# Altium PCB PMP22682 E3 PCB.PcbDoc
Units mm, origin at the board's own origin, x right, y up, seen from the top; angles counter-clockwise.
Board outline 97.75 x 106 mm, 6 copper layers (Top Layer, Signal Layer 1, Signal Layer 2, Signal Layer 3, Signal Layer 4, Bottom Layer), stack 2.5 mm thick; 97 components, 38 nets, 279 pads, 103 vias.
Unrouted connection lines stored in the file: 1.
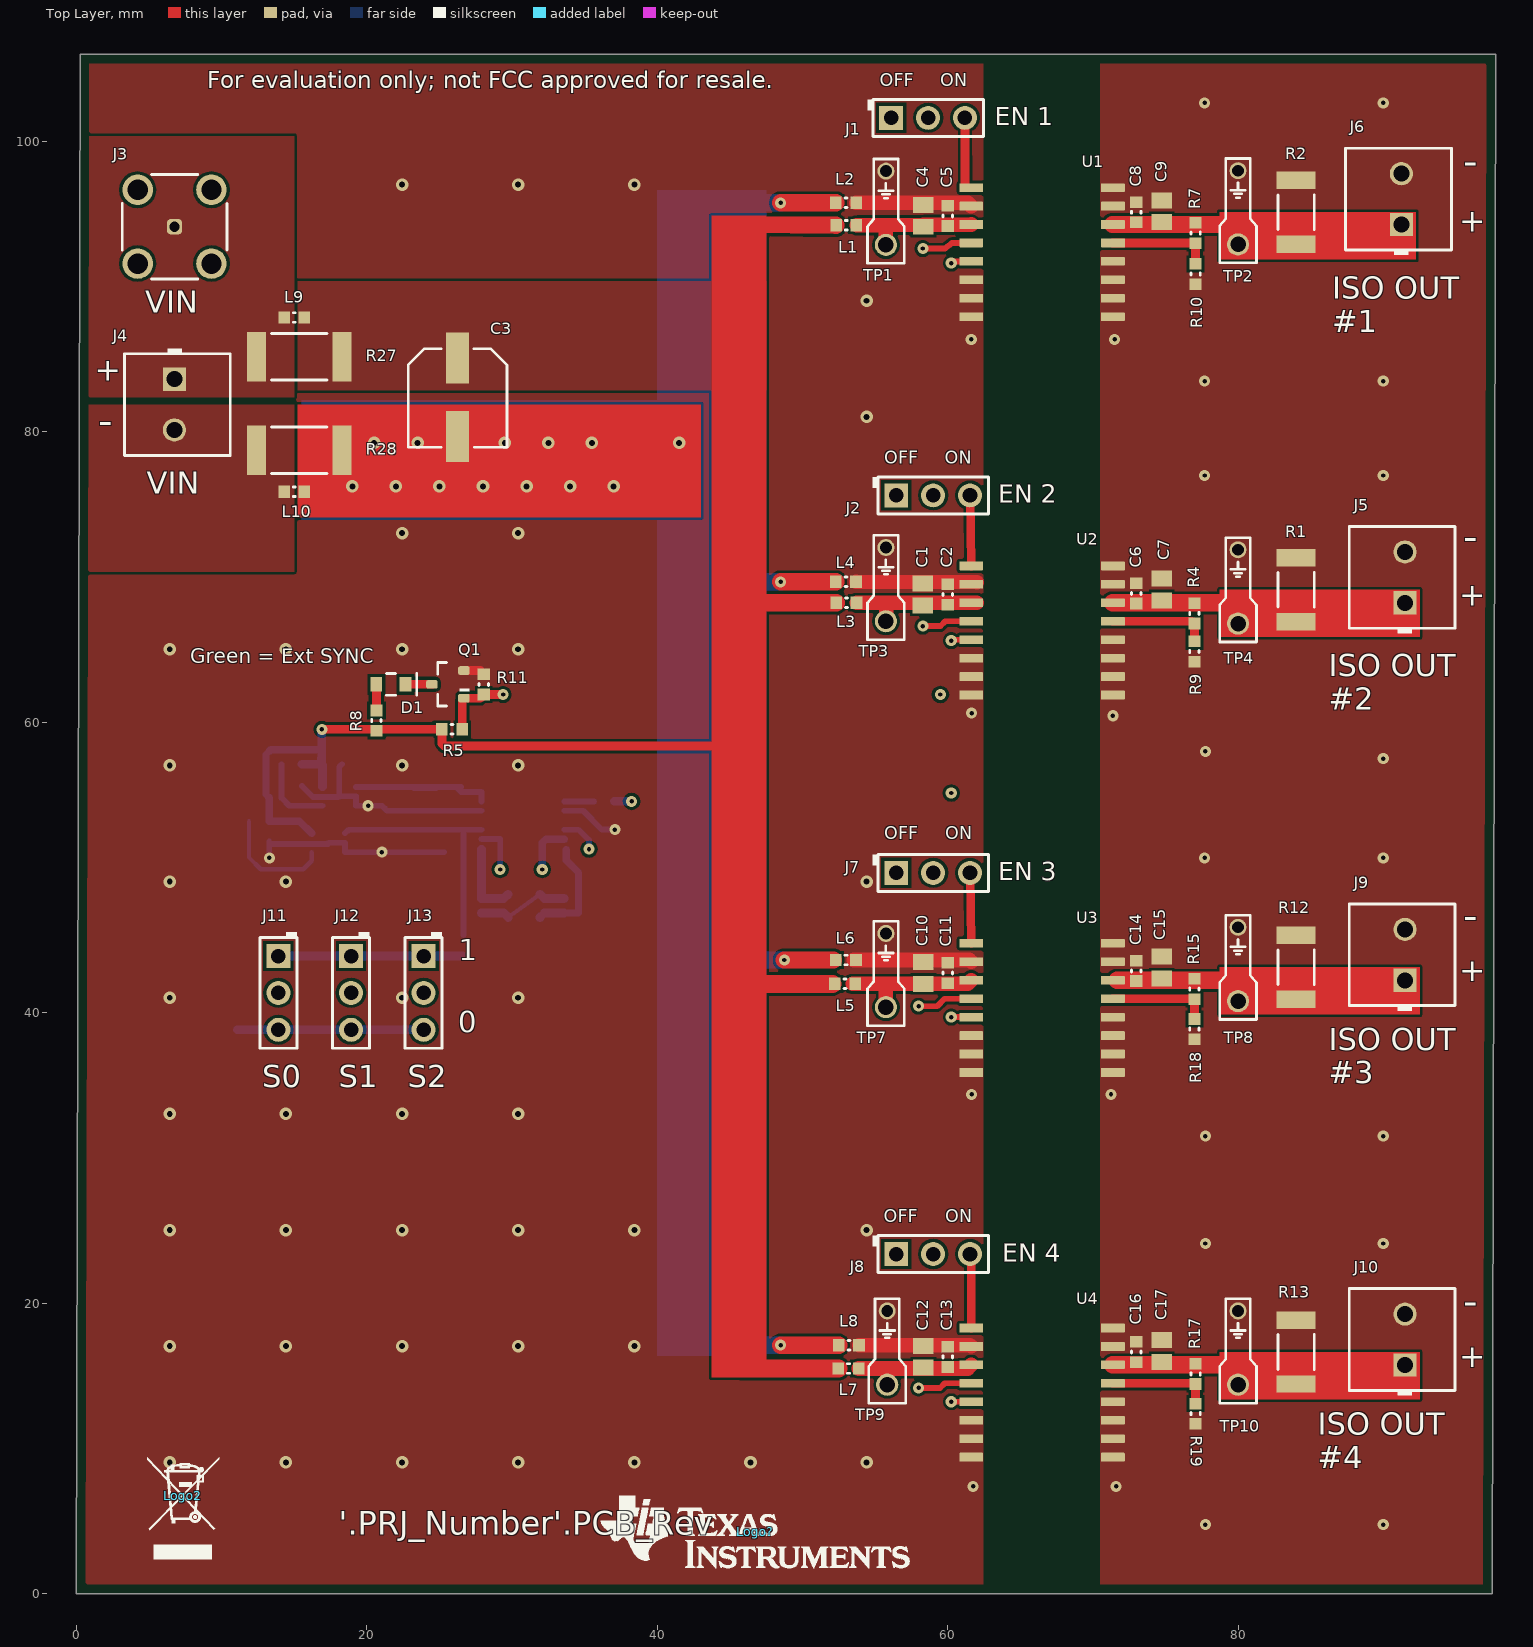
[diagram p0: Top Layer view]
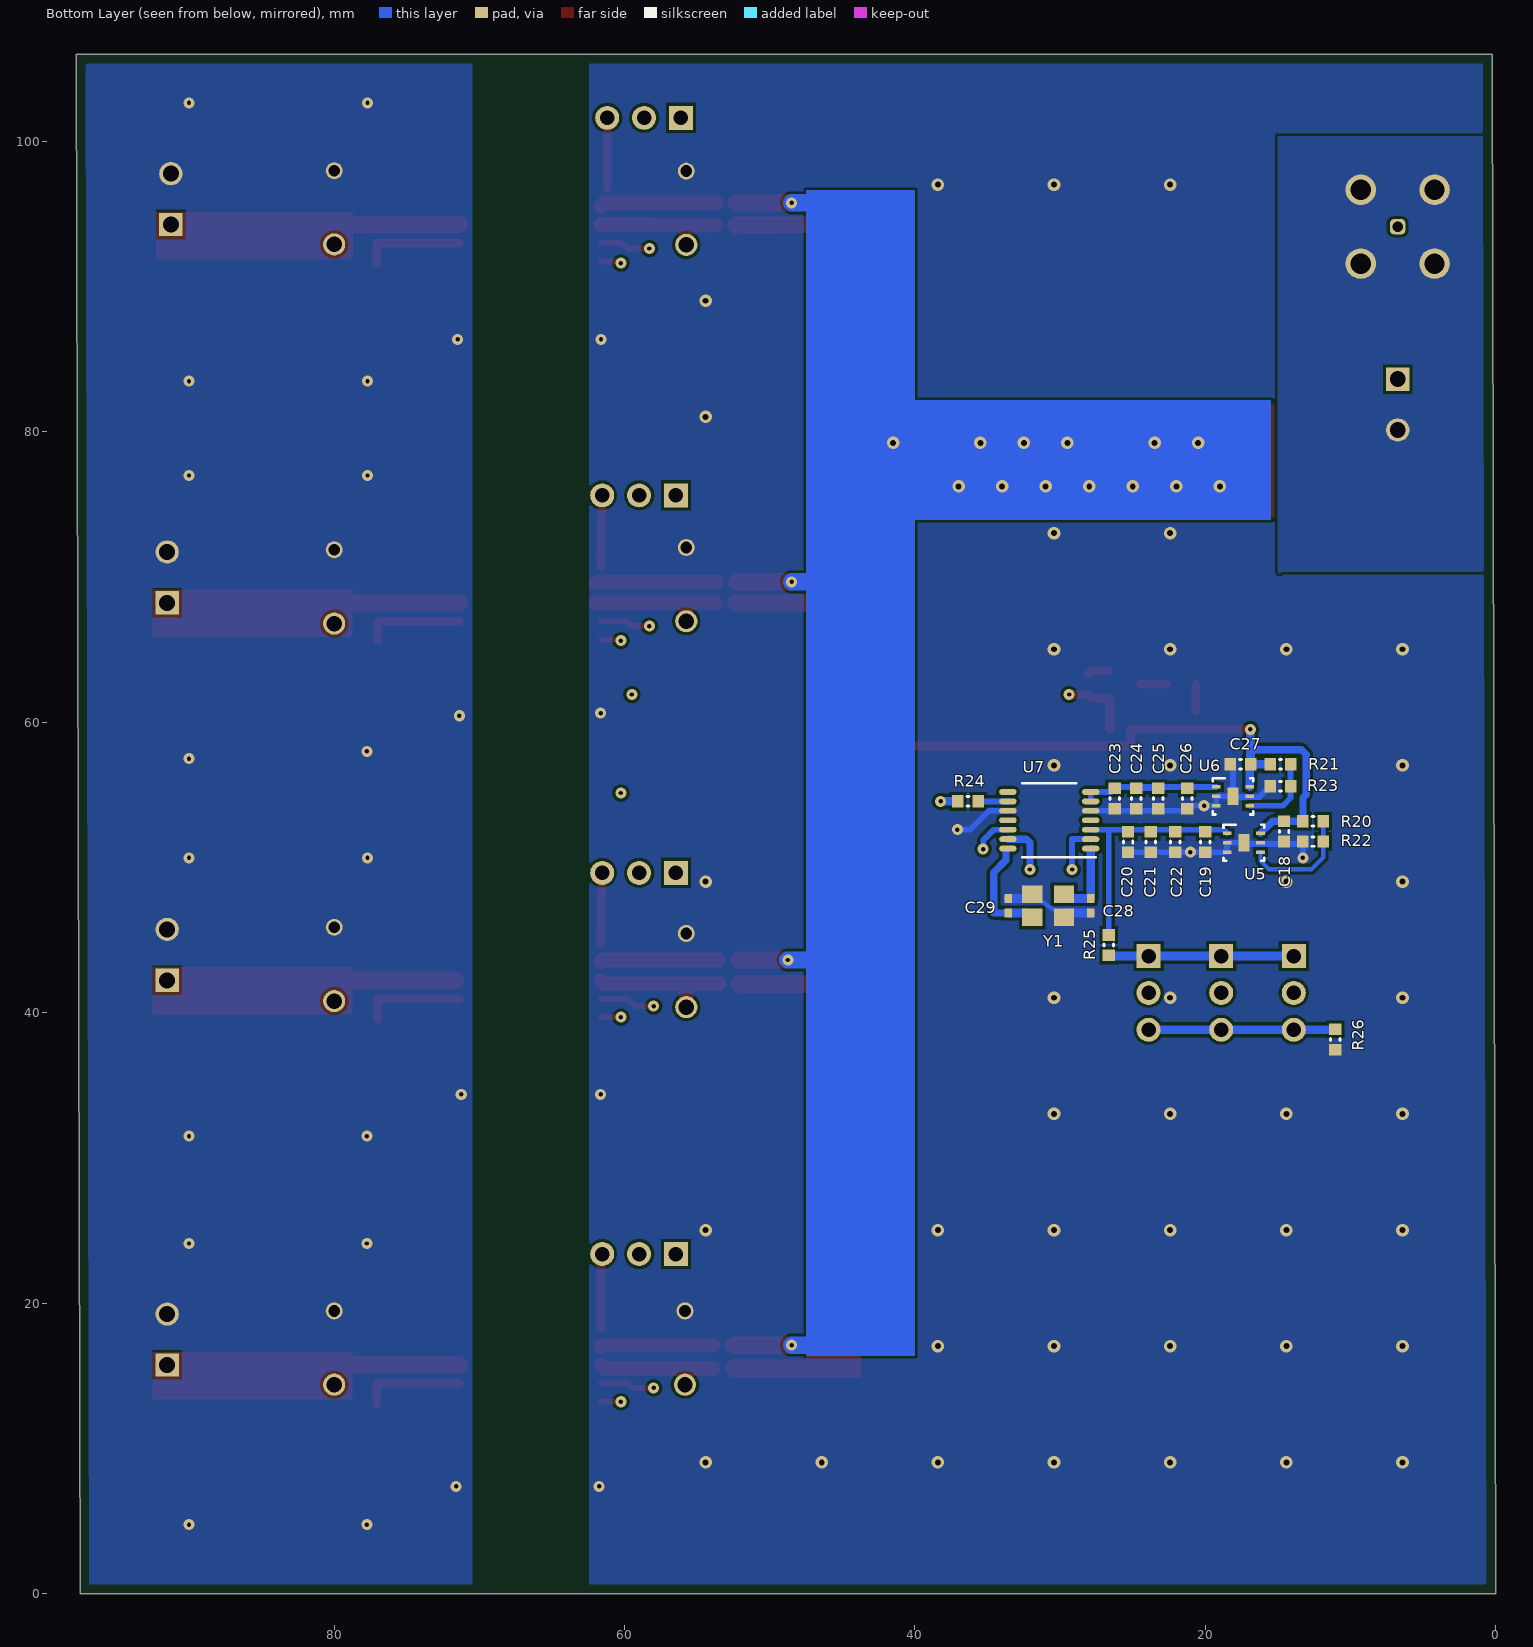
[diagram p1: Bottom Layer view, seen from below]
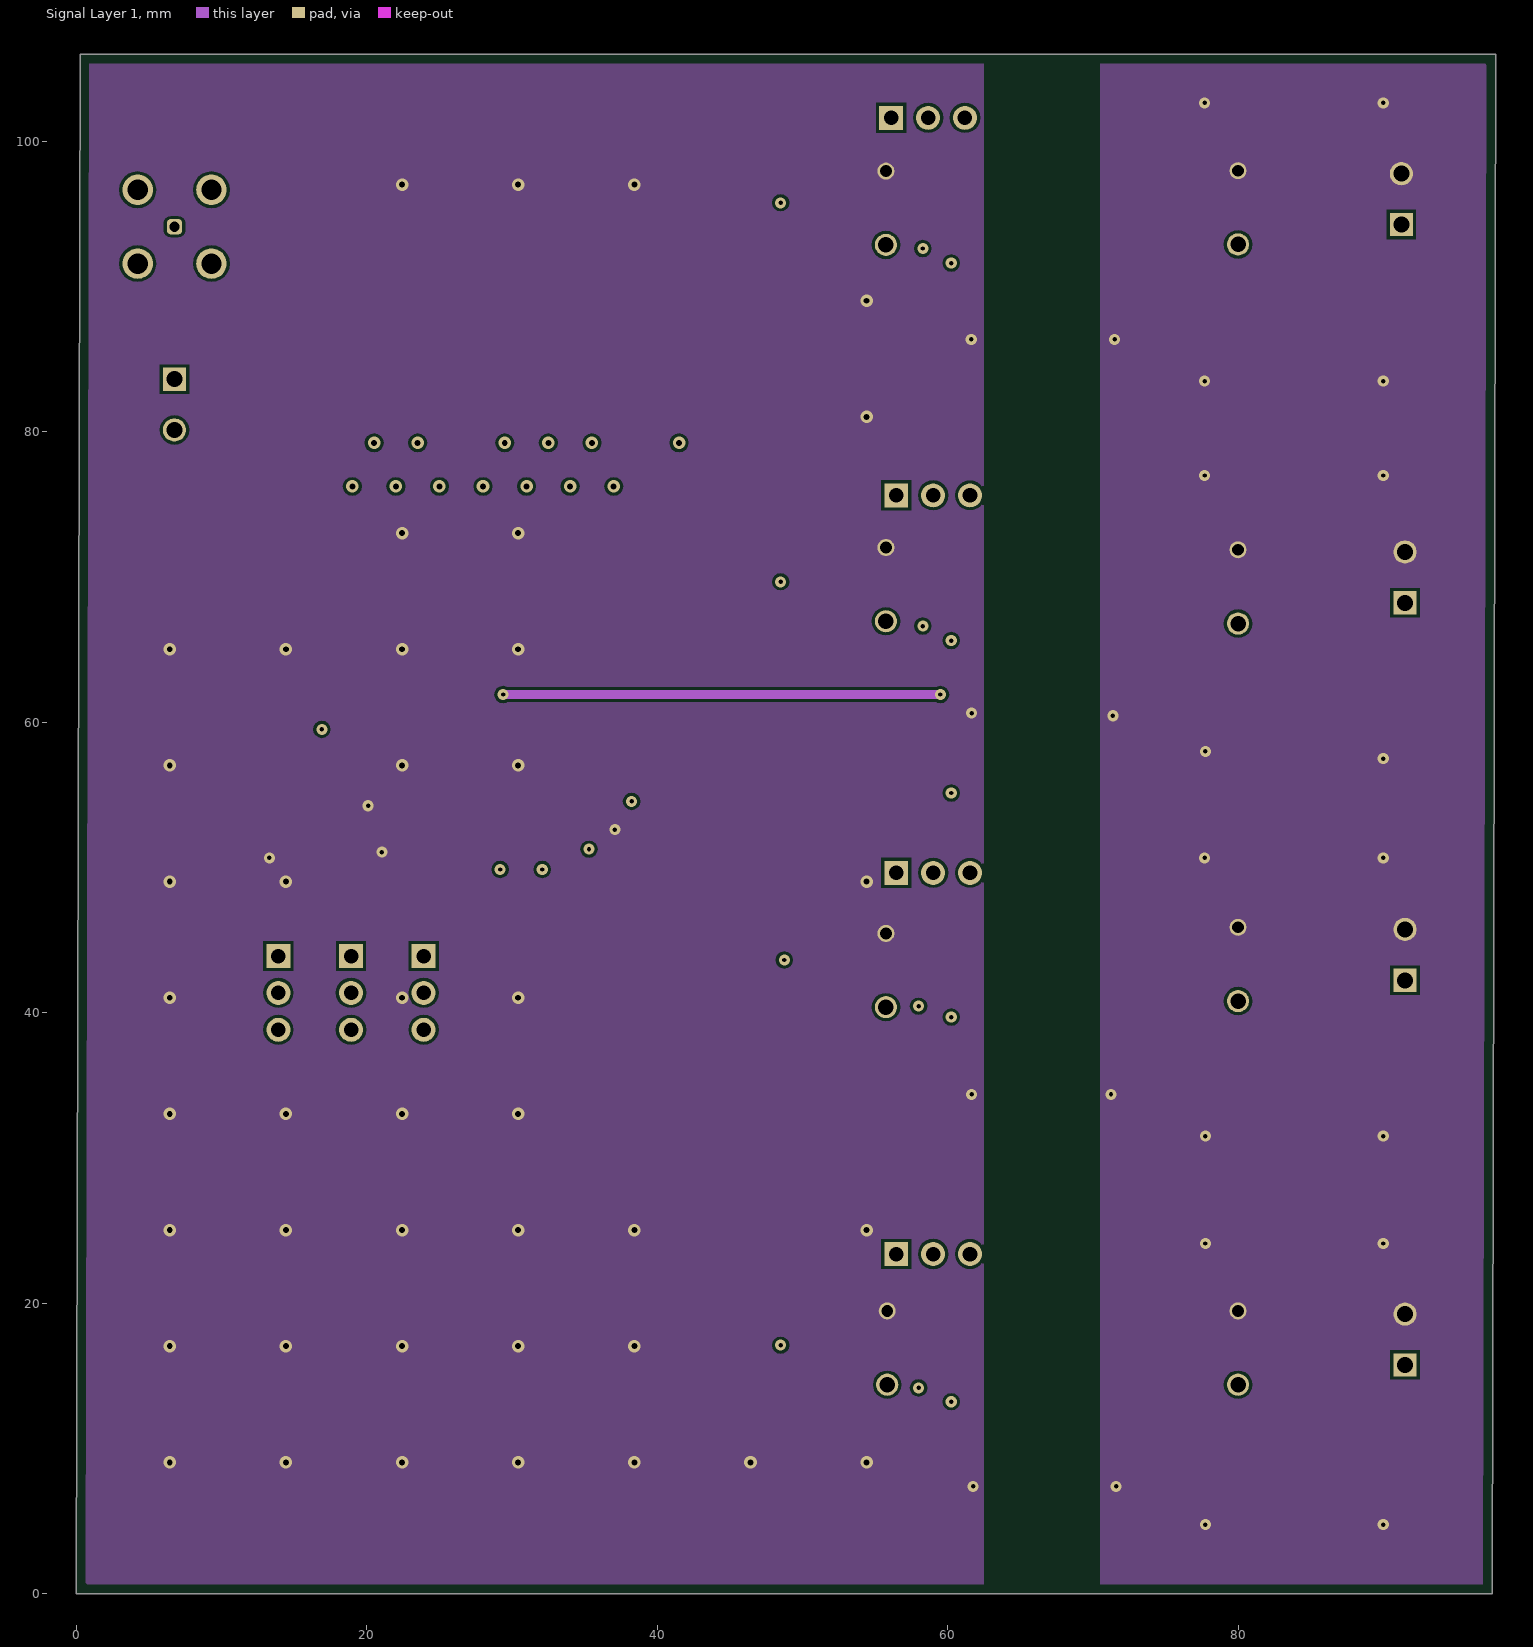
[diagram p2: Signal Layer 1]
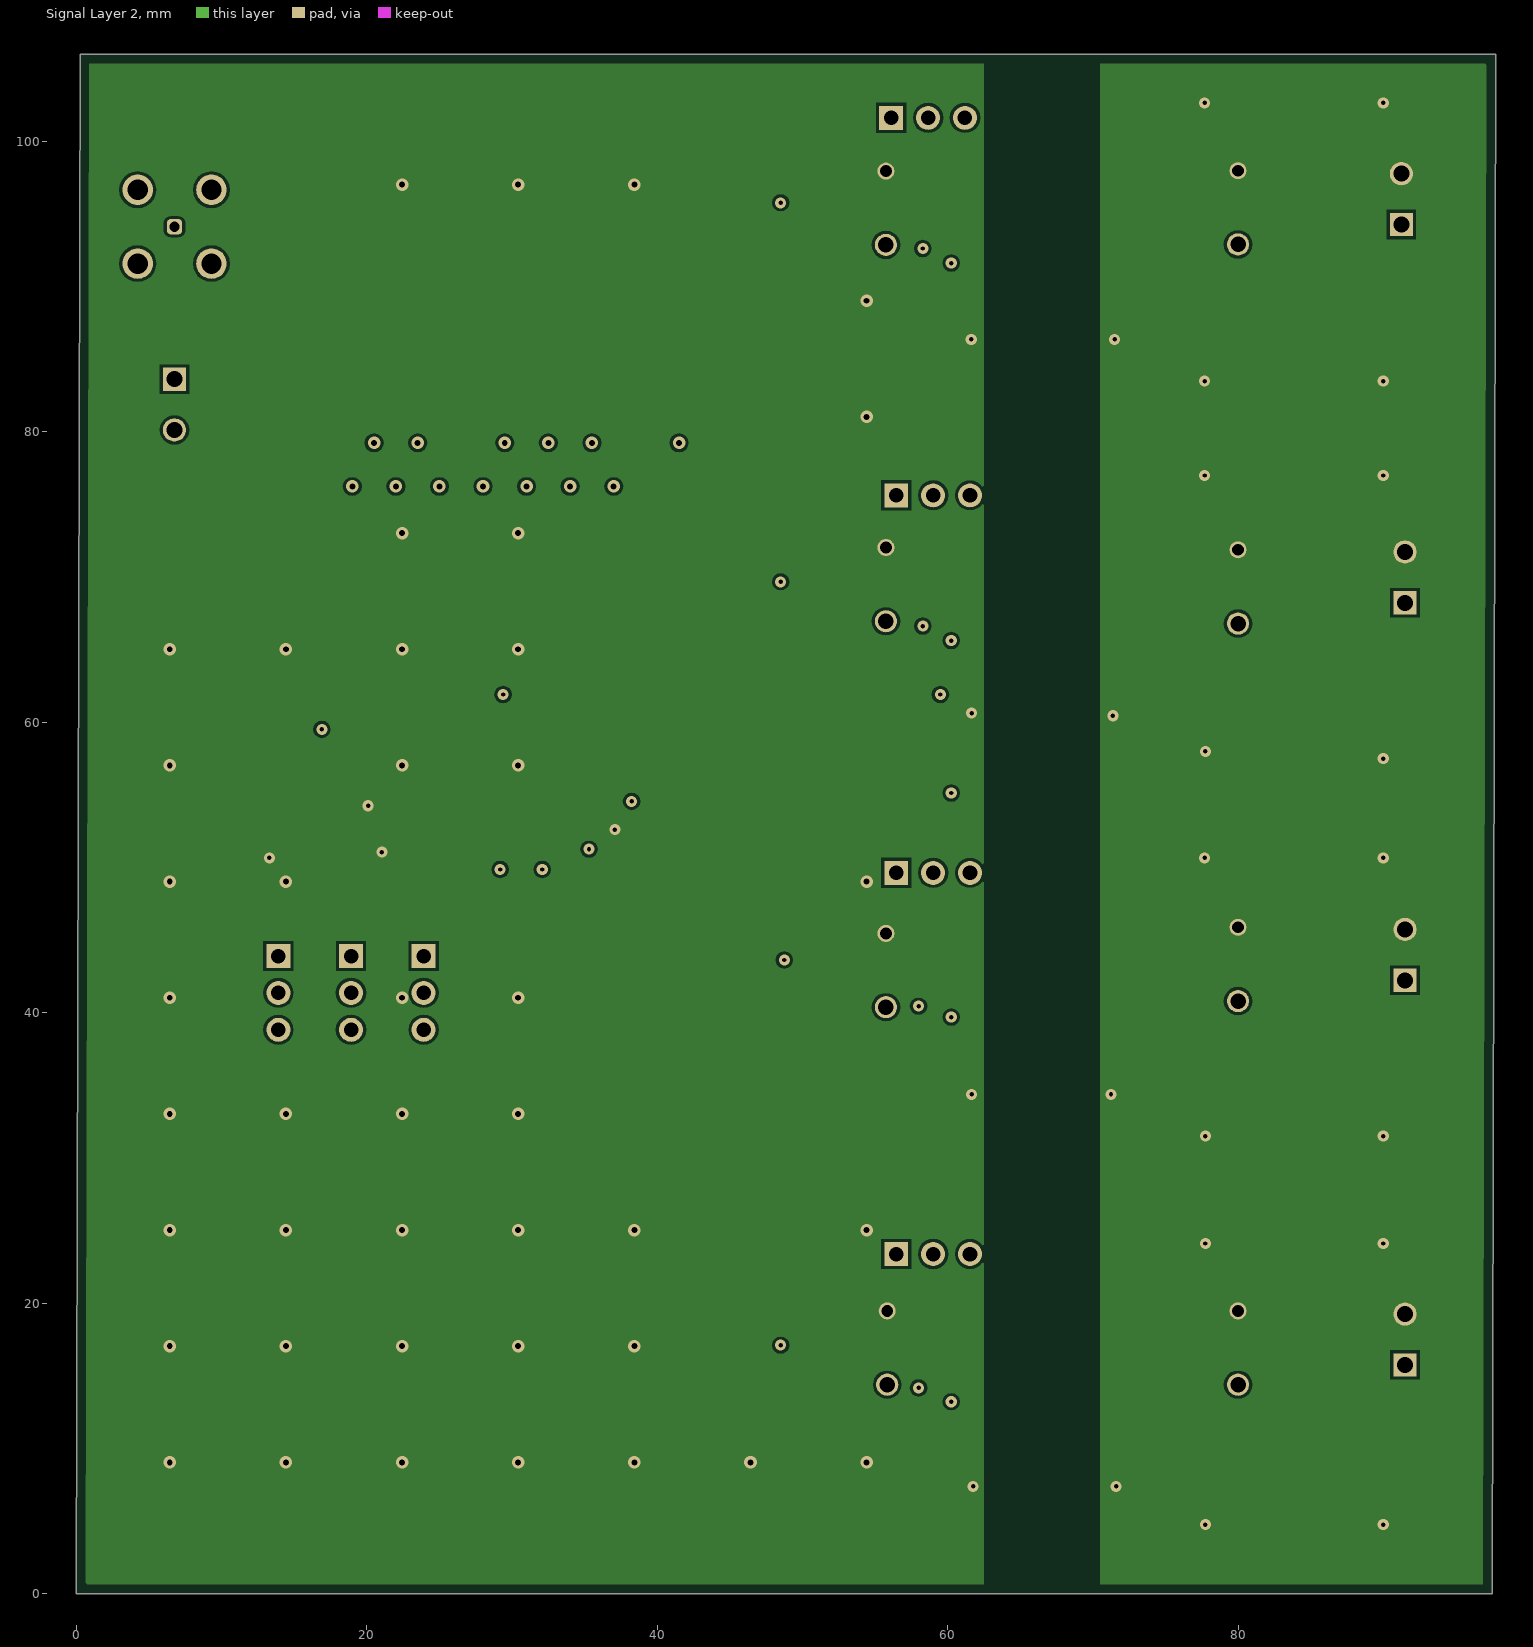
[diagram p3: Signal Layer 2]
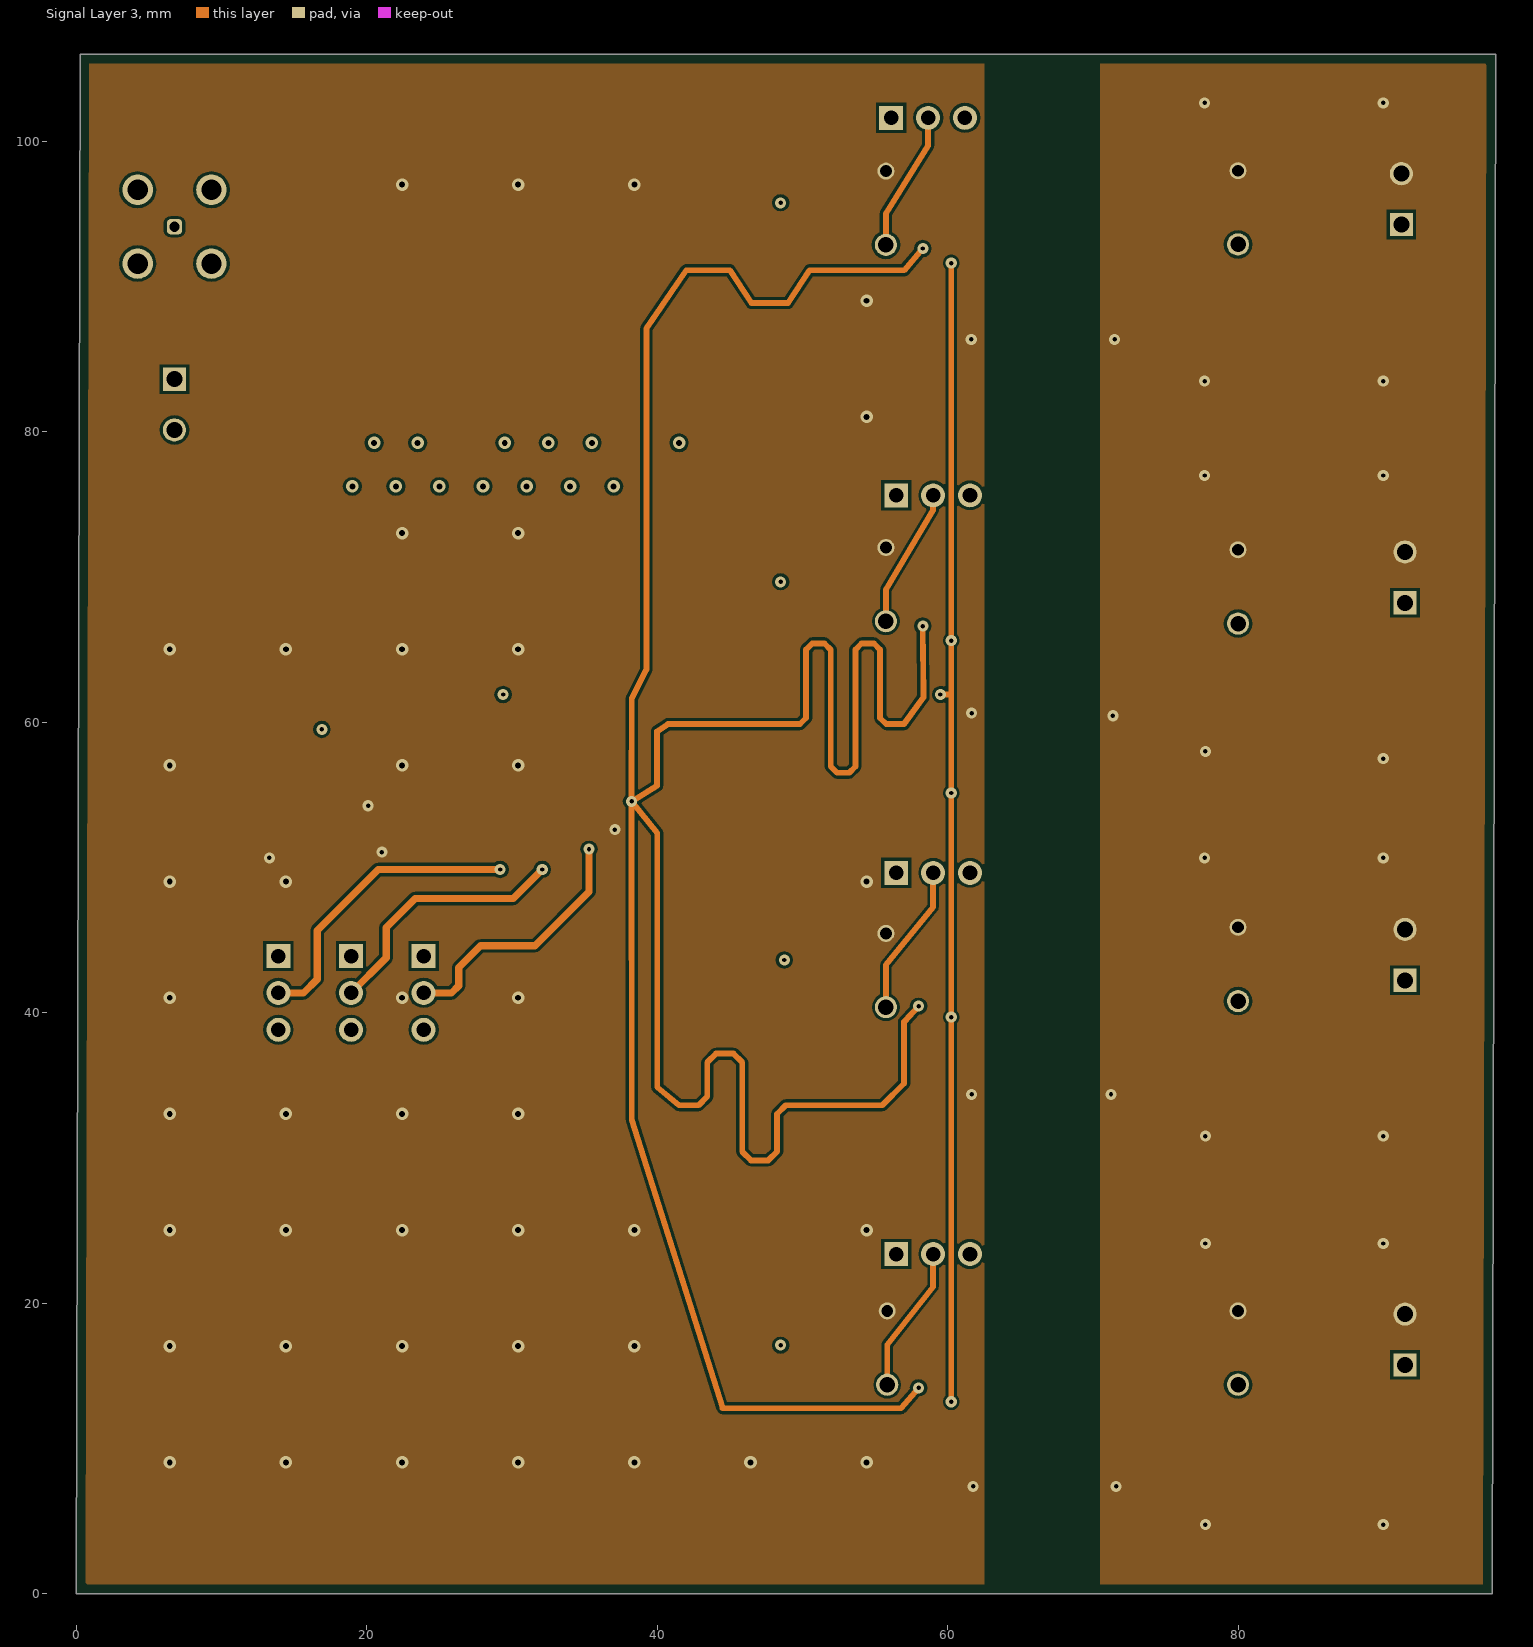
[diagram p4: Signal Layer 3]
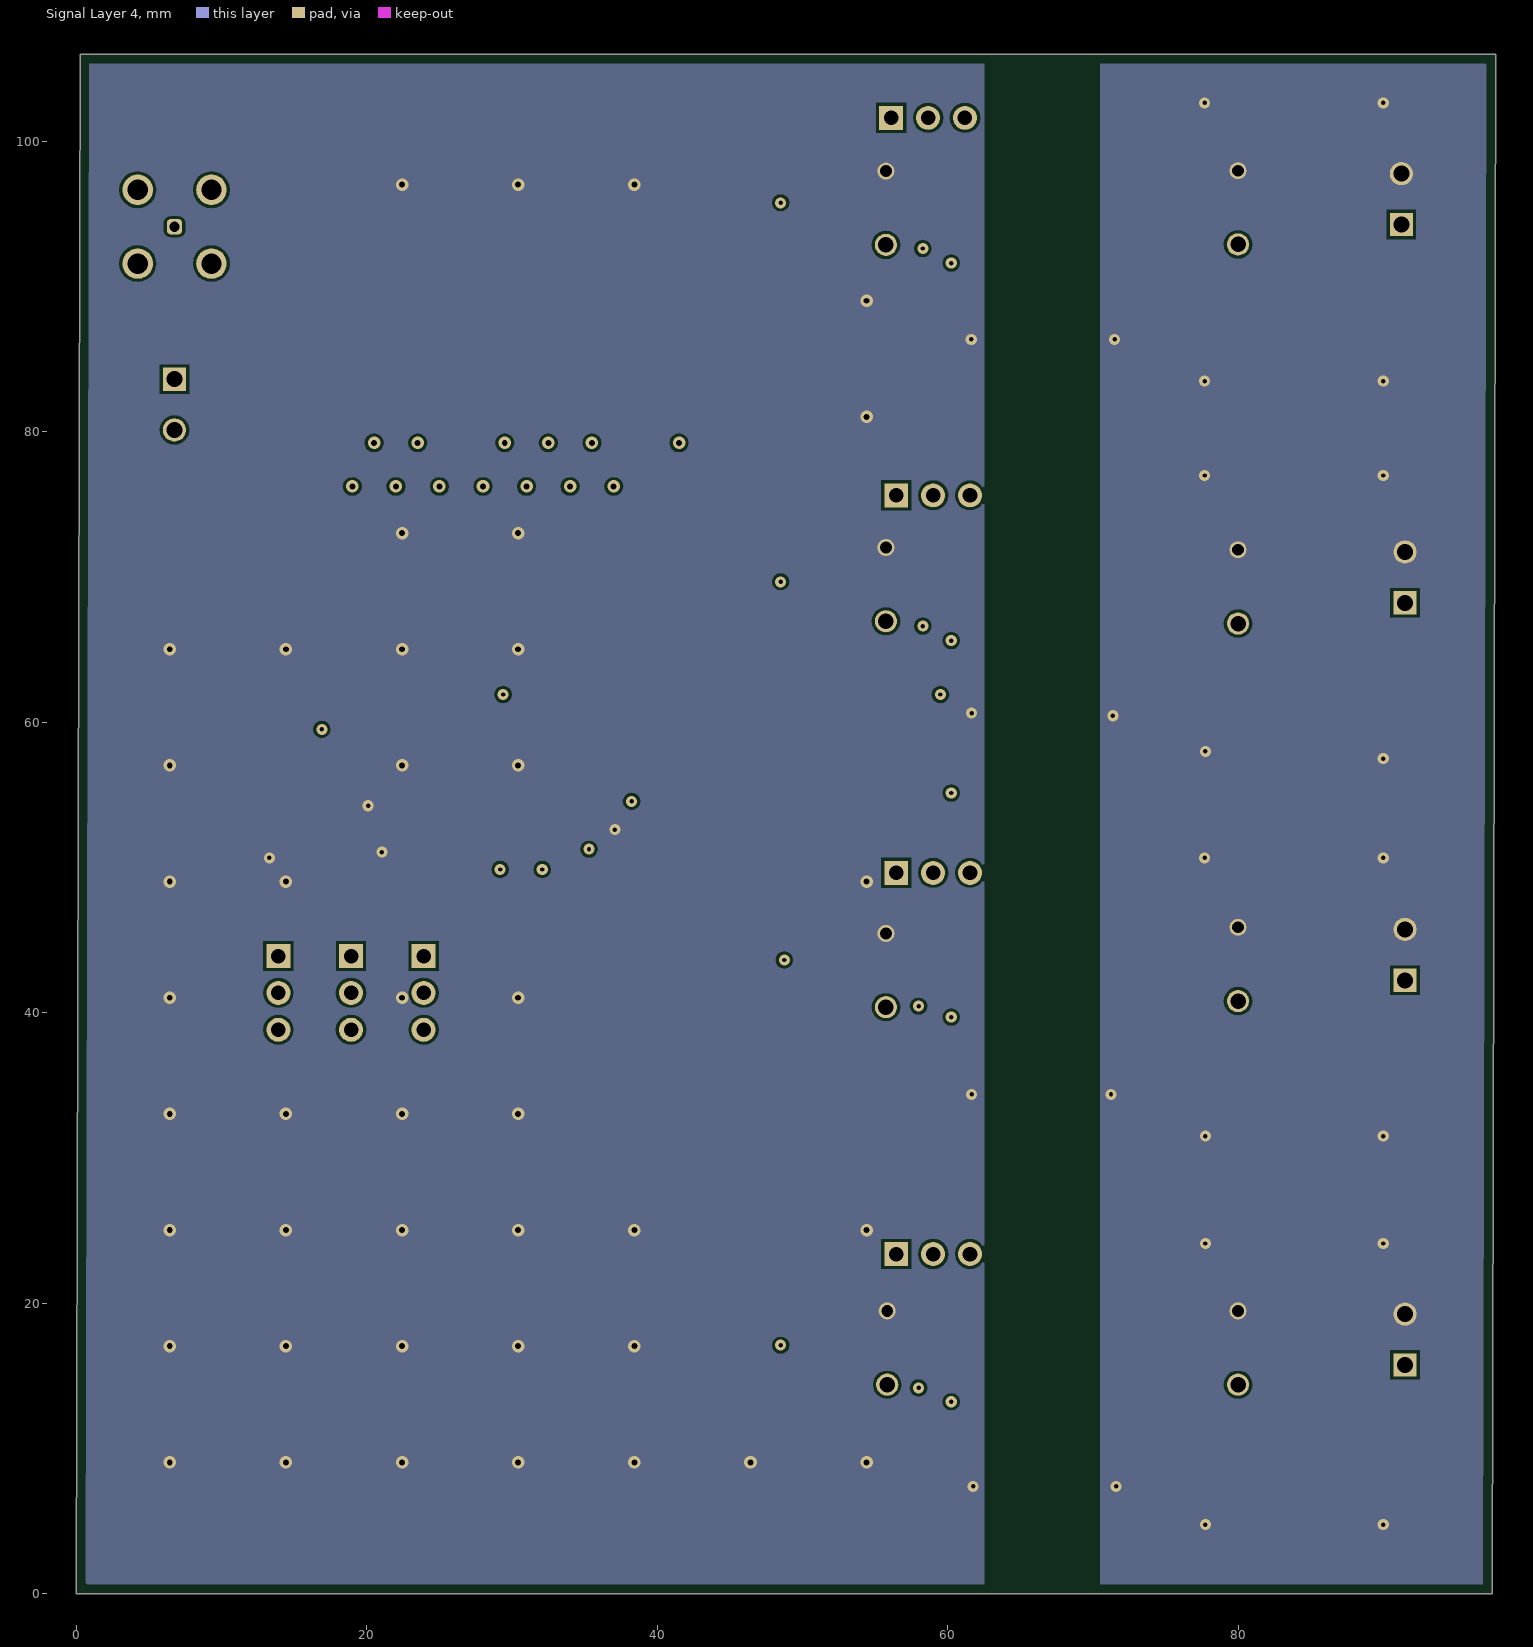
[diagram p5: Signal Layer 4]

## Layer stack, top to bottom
Top Solder: solder mask 0.0102, Solder Resist, Dk 3.5
Top Layer: signal copper 0.0356
Dielectric 1: core 0.4572, FR-4, Dk 4.2
Signal Layer 1: signal copper 0.0356
Dielectric 2: core 0.4572, FR-4, Dk 4.2
Signal Layer 2: signal copper 0.0356
Dielectric 3: core 0.4572, FR-4, Dk 4.2
Signal Layer 3: signal copper 0.036
Dielectric 4: core 0.4572, FR-4, Dk 4.2
Signal Layer 4: signal copper 0.036
Dielectric 5: core 0.4572, FR-4, Dk 4.2
Bottom Layer: signal copper 0.0356
Bottom Solder: solder mask 0.0102, Solder Resist, Dk 3.5

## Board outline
0,0 97.5,0 97.75,106 0.25,106

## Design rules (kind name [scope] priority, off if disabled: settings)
AcuteAngle [All] p1: minimum=4.50000000000000E+0001 checktracksonly=FALSE
AssemblyTestPointUsage [All] p1: valid=2
BoardOutlineClearance BoardOutlineClearance_MountingHoles [OnCopper and InComponentClass('Mounting Holes')] p1: gap=0.635 ignorepadtopadclearanceinfootprint=FALSE
BoardOutlineClearance BoardOutlineClearance_Poly [OnCopper and InPoly] p2: gap=0.635 ignorepadtopadclearanceinfootprint=FALSE
BoardOutlineClearance [OnCopper and Not InComponentClass('Logo') and not InComponentClass('FiducialMark') and not InRegion(1000,500,4000,800)] p3: gap=0.635 ignorepadtopadclearanceinfootprint=FALSE
Clearance Clearance_Keepouts [((IsTrack Or IsArc) And Not InPoly) And IsFree and IsKeepOut vs ((IsTrack Or IsArc) And Not InPoly) And IsFree and IsKeepOut] p1: gap=0 ignorepadtopadclearanceinfootprint=FALSE
Clearance Clearance_Poly [InPolygon] p2: gap=0.203 ignorepadtopadclearanceinfootprint=FALSE except(0: Arc-Hole Track-Hole SMDPad-Hole THPad-Hole Via-Hole Fill-Hole Poly-Hole Region-Hole Text-Hole)
Clearance [All] p3: gap=0.2 ignorepadtopadclearanceinfootprint=FALSE except(0: Arc-Hole Track-Hole SMDPad-Hole THPad-Hole Via-Hole Fill-Hole Poly-Hole Region-Hole Text-Hole)
ComponentClearance ComponentClearance_MountingHoles_FiducialMarks [InComponentClass('Mounting Holes') vs InComponentClass('FiducialMark')] p1: gap=1.27 collisioncheckmode=3 verticalgap=0.254 showdistances=FALSE
ComponentClearance ComponentClearance_Shunt [InComponentClass('Header') vs InComponentClass('Shunt')] p2: gap=0 collisioncheckmode=3 verticalgap=0 showdistances=FALSE
ComponentClearance ComponentClearance_Logo [InComponentClass('Logo')] p3: gap=1.27 collisioncheckmode=3 verticalgap=0.254 showdistances=FALSE
ComponentClearance ComponentClearance_ScrewToNut [(HasFootprint('NY PMS 440 0025 PH')) vs (HasFootprint('Keystone_1902C'))] p4: gap=0.127 collisioncheckmode=3 verticalgap=0.254 showdistances=FALSE
ComponentClearance ComponentClearance_MountingHoles [InComponentClass('Mounting Holes')] p5: gap=6.35 collisioncheckmode=3 verticalgap=2540 showdistances=FALSE
ComponentClearance ComponentClearance_SmallPassives [HasFootprint('0201*') or HasFootprint('0402*') or HasFootprint('0508') or HasFootprint('0603*') or HasFootprint('0612') or HasFootprint('0805*') or HasFootprint('0815*') or HasFootprint('0830*') or HasFootprint('1206*') or HasFootprint('1210*') or HasFootprint('1808*') or HasFootprint('1812*') or HasFootprint('1825*') or HasFootprint('2010*') or HasFootprint('2220*') or HasFootprint('2225*') or HasFootprint('2512*') or HasFootprint('2728*') or HasFootprint('3518*') vs HasFootprint('0201*') or HasFootprint('0402*') or HasFootprint('0508') or HasFootprint('0603*') or HasFootprint('0612') or HasFootprint('0805*') or HasFootprint('0815*') or HasFootprint('0830*') or HasFootprint('1206*') or HasFootprint('1210*') or HasFootprint('1808*') or HasFootprint('1812*') or HasFootprint('1825*') or HasFootprint('2010*') or HasFootprint('2220*') or HasFootprint('2225*') or HasFootprint('2512*') or HasFootprint('2728*') or HasFootprint('3518*')] p6: gap=0.38 collisioncheckmode=3 verticalgap=0.254 showdistances=FALSE
ComponentClearance ComponentClearance_THtoSMT [IsThruComponent vs IsSMTComponent] p7: gap=0.381 collisioncheckmode=3 verticalgap=0.762 showdistances=FALSE
ComponentClearance ComponentClearance_THtoTH [IsThruComponent vs IsThruComponent] p8: gap=0.381 collisioncheckmode=3 verticalgap=0.762 showdistances=FALSE
ComponentClearance [All] p9: gap=0.381 collisioncheckmode=3 verticalgap=0.254 showdistances=FALSE
DiffPairsRouting [All] p1: maxlimit=2.54 minlimit=0.254 mostfreqgap=0.254 toplayer_minwidth=0.381 toplayer_maxwidth=0.381 toplayer_prefwidth=0.381 midlayer1_minwidth=0.381 midlayer1_maxwidth=0.381 midlayer1_prefwidth=0.381 midlayer2_minwidth=0.381 midlayer2_maxwidth=0.381 midlayer2_prefwidth=0.381 midlayer3_minwidth=0.381 midlayer3_maxwidth=0.381 midlayer3_prefwidth=0.381 midlayer4_minwidth=0.381 midlayer4_maxwidth=0.381 midlayer4_prefwidth=0.381 bottomlayer_minwidth=0.381 bottomlayer_maxwidth=0.381 bottomlayer_prefwidth=0.381 maxuncoupledlength=25.4
FabricationTestPointUsage TestPointUsage [All] p1: valid=2 allowmultiple=FALSE
FabricationTestpoint Testpoint [All] p1: side=3 testpointundercomponent=TRUE minsize=1.016 maxsize=2.54 preferedsize=1.524 minholesize=0 maxholesize=1.016 preferedholesize=0.813 testpointgrid=0.025 allowsidetop=TRUE allowsidebottom=TRUE usegrid=TRUE gridtolerance=0
FanoutControl Fanout_LCC [IsLCC] p1: bgadir=Out bgaviamode=Centered fanoutstyle=Auto fanoutdirection=Alternating viagrid=0.025 // Fanout_LCC (Default Rule)
FanoutControl Fanout_BGA [IsBGA] p2: bgadir=Out bgaviamode=Centered fanoutstyle=Auto fanoutdirection=Alternating viagrid=0.025 // Fanout_BGA (Default Rule)
FanoutControl Fanout_Default [All] p4: bgadir=Out bgaviamode=Centered fanoutstyle=Auto fanoutdirection=Alternating viagrid=0.025 // Fanout_Default (Default Rule)
FanoutControl Fanout_Small [(CompPinCount < 5)] p5: bgadir=Out bgaviamode=Centered fanoutstyle=Auto fanoutdirection=OutThenIn viagrid=0.025 // Fanout_Small (Default Rule)
HoleSize [All] p1: absolutevalues=TRUE maxlimit=6.375 minlimit=0.2 maxpercent=80.000 minpercent=20.000
MinimumAnnularRing MinimumAnnularRing_ThermalPadVias [IsVia and InAnyComponent] p1: minimumring=0.15
MinimumAnnularRing [All] p2: minimumring=0.203
MinimumSolderMaskSliver MinimumSolderMaskSliver_Logo [InComponentClass('Logo') vs InComponentClass('Logo')] p1: minsoldermaskwidth=0.018
MinimumSolderMaskSliver [All] p2: minsoldermaskwidth=0.1
PlaneConnect [All] p1: planeconnectstyle=Direct reliefexpansion=0.254 reliefentries=4 reliefconductorwidth=0.254 reliefairgap=0.254
PolygonConnect [All] p1: connectstyle=Direct reliefconductorwidth=0.254 reliefentries=4 polygonreliefangle="90 Angle" airgapwidth=0.254
RoutingVias ThermalPadVias [IsVia and InAnyComponent] p1: holewidth=0.2 width=0.5 viastyle="Through Hole" minholewidth=0.2 minwidth=0.5 maxholewidth=0.33 maxwidth=0.6
RoutingVias [All] p2: holewidth=0.406 width=0.864 viastyle="Through Hole" minholewidth=0.2 minwidth=0.66 maxholewidth=1.016 maxwidth=1.651
SilkToBoardRegionClearance [Not ((IsComment or IsDesignator) And (Hide <> 'False')) and not InRegion(1000,500,4000,800)] p1:
SilkToSilkClearance SilkToSilkClearance_Pb-FreeLogo [(HasFootprint('Pb-Free_Overlay_Medium') OR HasFootprint('Pb-Free_Overlay_Small')) vs (HasFootprint('Pb-Free_Overlay_Medium') OR HasFootprint('Pb-Free_Overlay_Small'))] p1: silktosilkclearance=0
SilkToSilkClearance [All] p2: silktosilkclearance=0.102
SilkToSolderMaskClearance SilkToComponentPadClearance [IsPad and InAnycomponent] p1: minsilkscreentomaskgap=0.127 clearancetoexposedcopper=TRUE
SilkToSolderMaskClearance "Silk to Solder Mask Opening" [All] p2: minsilkscreentomaskgap=0.102 clearancetoexposedcopper=FALSE
SolderMaskExpansion [All] p1: expansion=0.05
Width [All] p1: maxlimit=2.54 minlimit=0.152 preferedwidth=0.254 checkconnectedcopper=TRUE
15 further rules are at their usual default settings.

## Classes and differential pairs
component class Logo: Logo?
component class Header: J1 J2 J7 J8 J11 J12 J13

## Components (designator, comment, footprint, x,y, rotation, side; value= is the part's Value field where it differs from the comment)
C1 "CL21B106KOQNNNE" 0805L 58.29,68.804 r90 top value=10uF
C2 "C1608X7R1H104K080AA" 0603L 60,68.804 r90 top value=0.1uF
C3 "EMVA100ADA101MF55G" CAPSMT_62_F55 26.25,82.384 r270 top value=100uF
C4 "CL21B106KOQNNNE" 0805L 58.33,94.884 r90 top value=10uF
C5 "C1608X7R1H104K080AA" 0603L 60,94.884 r90 top value=0.1uF
C6 "C1608X7R1H104K080AA" 0603L 73,68.884 r90 top value=0.1uF
C7 "CL21B106KOQNNNE" 0805L 74.75,69.154 r90 top value=10uF
C8 "C1608X7R1H104K080AA" 0603L 73,95.134 r90 top value=0.1uF
C9 "CL21B106KOQNNNE" 0805L 74.75,95.205 r90 top value=10uF
C10 "CL21B106KOQNNNE" 0805L 58.33,42.738 r90 top value=10uF
C11 "C1608X7R1H104K080AA" 0603L 60,42.738 r90 top value=0.1uF
C12 "CL21B106KOQNNNE" 0805L 58.33,16.304 r90 top value=10uF
C13 "C1608X7R1H104K080AA" 0603L 60,16.304 r90 top value=0.1uF
C14 "C1608X7R1H104K080AA" 0603L 73,42.884 r90 top value=0.1uF
C15 "CL21B106KOQNNNE" 0805L 74.75,43.109 r90 top value=10uF
C16 "C1608X7R1H104K080AA" 0603L 73,16.629 r90 top value=0.1uF
C17 "CL21B106KOQNNNE" 0805L 74.75,16.7 r90 top value=10uF
C18 "GCM188R71C474KA55D" 0603L 14.582,52.492 r270 bottom value=0.47uF
C19 "GCM188R71C474KA55D" 0603L 20,51.758 r270 bottom value=0.47uF
C20 "GCM188R71C105MA64D" 0603L 25.325,51.758 r270 bottom value=1uF
C21 "GCM188R71C104KA37J" 0603L 23.75,51.758 r270 bottom value=0.1uF
C22 "CGA3E2X7R2A103K080AA" 0603L 22.075,51.758 r270 bottom value=0.01uF
C23 "GCM188R71C105MA64D" 0603L 26.25,54.758 r270 bottom value=1uF
C24 "GCM188R71C104KA37J" 0603L 24.75,54.758 r270 bottom value=0.1uF
C25 "CGA3E2X7R2A103K080AA" 0603L 23.25,54.758 r270 bottom value=0.01uF
C26 "GCM188R71C474KA55D" 0603L 21.25,54.758 r270 bottom value=0.47uF
C27 "GCM188R71C474KA55D" 0603L 17.582,57.117 r0 bottom value=0.47uF
C28 "C0402C100C8GACTU" 0402L 27.9,47.367 r270 bottom value=10pF
C29 "C0402C100C8GACTU" 0402L 33.582,47.367 r90 bottom value=10pF
D1 "LP M67K-D2G1-25-Z" LP-M67K_Green 21.66,62.617 r0 top value=Green
J1 "5-146278-3" TE_5-146278-3 58.655,101.634 r0 top
J2 "5-146278-3" TE_5-146278-3 59,75.634 r0 top
J3 "142138-75" Amphenol_142138 6.755,94.136 r0 top
J4 "0393570002" MOLEX_39357-0002 6.75,81.886 r270 top
J5 "0393570002" MOLEX_39357-0002 91.5,69.984 r90 top
J6 "0393570002" MOLEX_39357-0002 91.25,96.039 r90 top
J7 "5-146278-3" TE_5-146278-3 59,49.634 r0 top
J8 "5-146278-3" TE_5-146278-3 59,23.384 r0 top
J9 "0393570002" MOLEX_39357-0002 91.5,43.988 r90 top
J10 "0393570002" MOLEX_39357-0002 91.5,17.498 r90 top
J11 "5-146278-3" TE_5-146278-3 13.91,41.365 r270 top
J12 "5-146278-3" TE_5-146278-3 18.91,41.365 r270 top
J13 "5-146278-3" TE_5-146278-3 23.91,41.365 r270 top
L1 "BLM18HE152SN1D" 0603L 53.016,94.234 r0 top value="1500 ohm"
L2 "BLM18HE152SN1D" 0603L 53,95.784 r0 top value="1500 ohm"
L3 "BLM18HE152SN1D" 0603L 53.026,68.234 r0 top value="1500 ohm"
L4 "BLM18HE152SN1D" 0603L 52.989,69.679 r0 top value="1500 ohm"
L5 "BLM18HE152SN1D" 0603L 52.929,41.988 r0 top value="1500 ohm"
L6 "BLM18HE152SN1D" 0603L 52.991,43.634 r0 top value="1500 ohm"
L7 "BLM18HE152SN1D" 0603L 53.175,15.499 r0 top value="1500 ohm"
L8 "BLM18HE152SN1D" 0603L 53.199,17.104 r0 top value="1500 ohm"
L9 "BLM18KG601SN1D" 0603L 15,87.884 r0 top value="600 ohm"
L10 "BLM18KG601SN1D" 0603L 15,75.884 r0 top value="600 ohm"
Logo1 "FCC disclaimer" FCC_disclaimer 26.25,129.25 r0 top
Logo2 "WEEE logo" WEEE_Minimum 7.309,6.75 r0 top
Logo? "Texas Instruments" TI_Stacked_Overlay_Small 46.75,4.25 r0 top
Q1 "2N7002Q-7-F" SOT-23L 25.582,62.617 r180 top value=60V
R1 "CRCW201051R1FKEF" 2010L 84,69.134 r270 top value=51.1
R2 "CRCW201051R1FKEF" 2010L 84,95.134 r270 top value=51.1
R4 "ERJ-3GEY0R00V" 0603L 77,67.512 r90 top value=0
R5 "CRCW060310K0FKEA" 0603L 25.87,59.517 r0 top value=10.0k
R7 "ERJ-3GEY0R00V" 0603L 77.075,93.708 r90 top value=0
R8 "CRCW0603499RFKEA" 0603L 20.66,60.117 r90 top value=499
R9 "ERJ-3GEY0R00V" 0603L 77,64.884 r90 top value=0
R10 "ERJ-3GEY0R00V" 0603L 77.075,90.884 r90 top value=0
R11 "RT0603DRE0751K1L" 0603L 28.057,62.617 r270 top value=51.1k
R12 "CRCW201051R1FKEF" 2010L 84,43.134 r270 top value=51.1
R13 "CRCW201051R1FKEF" 2010L 84,16.634 r270 top value=51.1
R15 "ERJ-3GEY0R00V" 0603L 77,41.634 r90 top value=0
R17 "ERJ-3GEY0R00V" 0603L 77.075,15.134 r90 top value=0
R18 "ERJ-3GEY0R00V" 0603L 77,38.867 r90 top value=0
R19 "ERJ-3GEY0R00V" 0603L 77.075,12.384 r90 top value=0
R20 "ERJ-3GEY0R00V" 0603L 12.582,53.192 r0 bottom value=0
R21 "ERJ-3GEY0R00V" 0603L 14.832,57.117 r180 bottom value=0
R22 "ERJ-3GEY0R00V" 0603L 12.582,51.792 r180 bottom value=0
R23 "ERJ-3GEY0R00V" 0603L 14.832,55.608 r0 bottom value=0
R24 "RC0603FR-0718RL" 0603L 36.35,54.558 r0 bottom value=18.0
R25 "RC0603FR-074K7L" 0603L 26.66,44.655 r270 bottom value=4.70k
R26 "RC0603FR-074K7L" 0603L 11.062,38.155 r270 bottom value=4.70k
R27 "3522ZR" 2512 15.343,85.17 r0 top value=0
R28 "3522ZR" 2512 15.343,78.732 r0 top value=0
TP1 "TESTPOINT_PIGTAIL" TESTPOINT_PIGTAIL 55.75,92.884 r180 top
TP2 "TESTPOINT_PIGTAIL" TESTPOINT_PIGTAIL 80,92.915 r180 top
TP3 "TESTPOINT_PIGTAIL" TESTPOINT_PIGTAIL 55.75,66.962 r180 top
TP4 "TESTPOINT_PIGTAIL" TESTPOINT_PIGTAIL 80,66.804 r180 top
TP7 "TESTPOINT_PIGTAIL" TESTPOINT_PIGTAIL 55.75,40.384 r180 top
TP8 "TESTPOINT_PIGTAIL" TESTPOINT_PIGTAIL 80,40.804 r180 top
TP9 "TESTPOINT_PIGTAIL" TESTPOINT_PIGTAIL 55.838,14.384 r180 top
TP10 "TESTPOINT_PIGTAIL" TESTPOINT_PIGTAIL 80,14.384 r180 top
U1 "UCC12050DVER" DVE0016A 66.5,92.384 r0 top
U2 "UCC12050DVER" DVE0016A 66.5,66.329 r0 top
U3 "UCC12050DVER" DVE0016A 66.5,40.333 r0 top
U4 "UCC12050DVER" DVE0016A 66.5,13.843 r0 top
U5 "LP5900SDX-1.8/NOPB" NGF0006A 17.35,51.708 r180 bottom
U6 "LP5900SDX-3.3/NOPB" NGF0006A 18.1,54.908 r180 bottom
U7 "CDCE913PWR" PW0014A_L 30.75,53.258 r0 bottom
Y1 "NX3225SA-16.000M-STD-CRS-2" NDK_NX3225SA 30.832,47.367 r270 bottom

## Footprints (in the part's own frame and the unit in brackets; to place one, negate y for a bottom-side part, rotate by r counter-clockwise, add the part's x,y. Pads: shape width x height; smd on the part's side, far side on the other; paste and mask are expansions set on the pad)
0402L [mm] "0402 from SM-752 data"
  rect 0.6x0.5 smd: 1(-0.5,0) 2(0.5,0)
  body extent -0.55,-0.3 0.55,0.3, height 0.6
0603L [mm] "0603 from SM-752 data"
  rect 0.8x0.85 smd: 1(-0.7,0) 2(0.7,0)
  silkscreen extent -0.07,-0.33 0.07,0.33, body extent -0.87,-0.47 0.87,0.47, height 1
0805L [mm] "0805 from SM-752 data"
  rect 1.1x1.4 smd: 1(-0.75,0) 2(0.75,0)
  body extent -1.1,-0.72 1.1,0.72, height 1.45
2010L [mm]
  rect 1.2x2.7 smd: 1(-2.2,0) 2(2.2,0)
  silkscreen extent -1.2,-1.25 1.2,1.25, body extent -2.73,-1.45 2.73,1.45, height 1.66
2512 [mm] "Chip Resistor, Body 6.3x3.2mm, IPC Medium Density"
  rect 1.3x3.4 smd: 1(-2.95,0) 2(2.95,0)
  silkscreen extent -1.9,-1.6 1.9,1.6, body extent -3.22,-1.67 3.22,1.67, height 0.71
Amphenol_142138 [mm] "JACK, 75 Ohm, TH"
  rrect50% 1.05x1.05 hole 0.7: 1(0,0)
  round 2.1 hole 1.4: 2(-2.54,2.54) 3(2.54,2.54) 4(2.54,-2.54) 5(-2.54,-2.54)
  silkscreen extent -3.6,-3.6 3.6,3.6, body extent -3.6,-3.6 3.6,3.6, height 7.8
CAPSMT_62_F55 [mm] "6.3 x 5.2mm:  Chemi-Con F55"
  rect 3.5x1.6 smd: 1(-2.7,0) 2(2.7,0)
  silkscreen extent -3.36,-3.4 3.44,3.4, body extent -3.4,-3.4 3.44,3.4, height 5.5
DVE0016A [mm] "SO-MOD-16"
  rrect17% 1.65x0.6 smd: 1(-4.875,4.445) 2(-4.875,3.175) 3(-4.875,1.905) 4(-4.875,0.635) 5(-4.875,-0.635) 6(-4.875,-1.905) 7(-4.875,-3.175) 8(-4.875,-4.445) 9(4.875,-4.445) 10(4.875,-3.175) 11(4.875,-1.905) 12(4.875,-0.635) 13(4.875,0.635) 14(4.875,1.905) 15(4.875,3.175) 16(4.875,4.445)
  body extent -5.17,-5.15 5.17,5.15, height 2.59
FCC_disclaimer [mm]
LP-M67K_Green [mm] "Osram"
  rect 0.8x1 smd: 1(-1,0) 2(1,0)
  silkscreen extent -0.3,-0.75 1.78,0.75, body extent -1.15,-0.75 1.15,0.75, height 1.4
MOLEX_39357-0002 [mm] "Terminal Block, 3.5 mm, 2x1, TH"
  rect 1.6x1.6 hole 1.1: 1(-1.75,0)
  round 1.6 hole 1.1: 2(1.75,0)
  silkscreen extent -3.86,-3.45 3.5,3.84, body extent -3.55,-3.45 3.56,3.84, height 8.51
NDK_NX3225SA [mm] "NDK"
  rect 1.2x1.4 smd: 1(-0.8,1.1) 2(-0.8,-1.1) 3(0.8,-1.1) 4(0.8,1.1)
  body extent -1.3,-1.65 1.3,1.65, height 0.7
NGF0006A [mm] "TI"
  rect 0.6x0.25 smd: 1(-1.15,0.65) 2(-1.15,0) 3(-1.15,-0.65) 4(1.15,-0.65) 5(1.15,0) 6(1.15,0.65)
  rect 0.75x1.2 smd paste-0.38: 7(0,0)
  silkscreen extent -1.4,-1.25 1.4,1.25, body extent -1.3,-1.15 1.3,1.15, height 0.81
PW0014A_L [mm] "TSOP, 14-Leads, Body 5x4.4mm, Pitch 0.65mm, IPC High Density"
  oval 1.2x0.4 smd: 1(-2.85,1.95) 2(-2.85,1.3) 3(-2.85,0.65) 4(-2.85,0) 5(-2.85,-0.65) 6(-2.85,-1.3) 7(-2.85,-1.95) 8(2.85,-1.95) 9(2.85,-1.3) 10(2.85,-0.65) 11(2.85,0) 12(2.85,0.65) 13(2.85,1.3) 14(2.85,1.95)
  silkscreen extent -3.2,-2.55 1.85,2.55, body extent -3.21,-2.5 3.21,2.5, height 1
SOT-23L [mm] "SOT23, 3-Leads, Body 2.9x1.3mm, Pitch 0.95mm, Lead Span 2.5mm, IPC High Density"
  rrect50% 0.8x0.6 smd: 1(-1.1,0.95) 2(-1.1,-0.95) 3(1.1,0)
  silkscreen extent -1.5,-1.5 0.7,1.5, body extent -1.16,-1.45 1.21,1.45, height 1
TE_5-146278-3 [mm] "TE CONNECTIVITY"
  rect 1.65x1.65 hole 1: 1(-2.54,0)
  round 1.65 hole 1: 2(0,0) 3(2.54,0)
  silkscreen extent -4.19,-1.27 3.81,1.27, body extent -3.68,-1.17 3.68,1.17, height 8.13
TESTPOINT_PIGTAIL [mil] "Pigtail"
  round 60 hole 42: 1(0,0)
  round 46 hole 32: 2(0,-200)
  silkscreen extent -50,-233 50,50
TI_Stacked_Overlay_Small [mm]
  silkscreen extent -10.63,-2.49 10.63,2.49
WEEE_Minimum [mm] "WEEElie bin"
  silkscreen extent -2.42,-4.38 2.52,2.65

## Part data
C1 C4 C7 C9 C10 C12 C15 C17: library part CMP-0007995-2, "CAP, CERM, 10 uF, 16 V, +/- 10%, X7R, 0805", Cap_Case=0805, Manufacturer="Samsung Electro-Mechanics", TempCo=X7R, Tolerance_%=10%, Value1=Unknown, Value2=16V, ValueDisplayed=10uF
C2 C5 C6 C8 C11 C13 C14 C16: library part CMP-0007044-5, "CAP, CERM, 0.1 uF, 50 V, +/- 10%, X7R, 0603", Cap_Case=0603, Manufacturer=TDK, Supplier Part Number 1=445-1314-1-ND, TempCo=X7R, Tolerance_%=10%, Value1="0.0296 ohm", Value2=50V, ValueDisplayed=0.1uF
C3: library part CMP-0010758-1, "CAP, AL, 100 uF, 10 V, +/- 20%, SMD", Cap_Case=F55, Manufacturer=Chemi-Con, Supplier Part Number 1=565-2075-1-ND, Tolerance_%=20%, Value1=Unknown, Value2=10V, ValueDisplayed=100uF
C18 C19 C26 C27: library part CMP-0007138-4, "CAP, CERM, 0.47 uF, 16 V, +/- 10%, X7R, AEC-Q200 Grade 1, 0603", Cap_Case=0603, Manufacturer=MuRata, Supplier Part Number 1=490-4775-1-ND, TempCo=X7R, Tolerance_%=10%, Value1=Unknown, Value2=16V, ValueDisplayed=0.47uF
C20 C23: library part CMP-0007137-5, "CAP, CERM, 1 uF, 16 V, +/- 20%, X7R, AEC-Q200 Grade 1, 0603", Cap_Case=0603, Manufacturer=MuRata, TempCo=X7R, Tolerance_%=20%, Value1=Unknown, Value2=16V, ValueDisplayed=1uF
C21 C24: library part CMP-0007135-4, "CAP, CERM, 0.1 uF, 16 V, +/- 10%, X7R, AEC-Q200 Grade 1, 0603", Cap_Case=0603, Manufacturer=MuRata, Supplier Part Number 1=490-8015-1-ND, TempCo=X7R, Tolerance_%=10%, Value1=Unknown, Value2=16V, ValueDisplayed=0.1uF
C22 C25: library part CMP-0007082-4, "CAP, CERM, 0.01 uF, 100 V, +/- 10%, X7R, AEC-Q200 Grade 1, 0603", Cap_Case=0603, Manufacturer=TDK, Supplier Part Number 1=445-5812-1-ND, TempCo=X7R, Tolerance_%=10%, Value1="0.235428 ohm", Value2=100V, ValueDisplayed=0.01uF
C28 C29: library part CMP-0064914-2, "CAP, CERM, 10 pF, 10 V,+/- 2.5%, C0G/NP0, 0402", Cap_Case=0402, Manufacturer=Kemet, Supplier Part Number 1=399-8939-1-ND, TempCo=C0G/NP0, Tolerance_%=2.5%, Value1=Unknown, Value2=10V, ValueDisplayed=10pF
D1: library part CMP-0002879-2, "LED, Green, SMD", Color=green, Manufacturer=OSRAM, Value1=W, Value2=1.8V
J1 J2 J7 J8 J11 J12 J13: library part CMP-0054951-1, "Header, 100mil, 3x1, Tin, TH", Manufacturer="TE Connectivity", Supplier Part Number 1=5-146278-3-ND
J3: library part CMP-0078748-1, "JACK, SMB, 75 Ohm, Gold, TH", Manufacturer="Amphenol RF", Supplier Part Number 1=ACX1313-ND
J4 J5 J6 J9 J10: library part CMP-0055341-2, "Terminal Block, 3.5 mm, 2x1, Tin, TH", Manufacturer=Molex, Supplier Part Number 1=WM7877-ND
L1 L2 L3 L4 L5 L6 L7 L8: library part CMP-0003349-2, "Ferrite Bead, 1500 ohm @ 100 MHz, 0.5 A, 0603", Manufacturer=MuRata, Supplier Part Number 1=490-5216-1-ND, Value1="0.5 ohm", Value2=0.5A, ValueDisplayed="1500 ohm"
L9 L10: library part CMP-0003351-2, "Ferrite Bead, 600 ohm @ 100 MHz, 1.3 A, 0603", Manufacturer=MuRata, Supplier Part Number 1=490-5258-1-ND, Value1="0.15 ohm", Value2=1.3A, ValueDisplayed="600 ohm"
Logo1: library part CMP-0074847-1, "FCC_disclaimer"
Logo2: library part CMP-0074769-1
Logo?: library part CMP-0074838-1, "Texas Instrument Corporate Signature"
Q1: library part CMP-0085603-1, "MOSFET, N-CH, 60 V, 0.115 A, AEC-Q101, SOT-23", Alternate Manufacturer=None, Manufacturer="Diodes Inc.", Value1="? ohm", Value2="0.223 nC"
R1 R2 R12 R13: library part CMP-0016433-3, "RES, 51.1, 1%, 0.75 W, AEC-Q200 Grade 0, 2010", Manufacturer=Vishay-Dale, Power_W=750mW, Supplier Part Number 1=541-51.1ACCT-ND, TempCo="100 ppm/C", Tolerance_%=1%, Value2=0.75W, Value_Code=51R1, ValueDisplayed=51.1
R4 R7 R9 R10 R15 R17 R18 R19 R20 R21 R22 R23: library part CMP-0025874-4, "RES, 0, 5%, 0.1 W, AEC-Q200 Grade 0, 0603", Manufacturer=Panasonic, Power_W=100mW, Supplier Part Number 1=P0.0GCT-ND, TempCo="600 ppm/C", Tolerance_%=5%, Value2=0.1W, Value_Code=0000, ValueDisplayed=0
R5: library part CMP-0021998-4, "RES, 10.0 k, 1%, 0.1 W, AEC-Q200 Grade 0, 0603", Manufacturer=Vishay-Dale, Power_W=100mW, Supplier Part Number 1=541-10.0KHCT-ND, TempCo="100 ppm/C", Tolerance_%=1%, Value2=0.1W, Value_Code=10k0, ValueDisplayed=10.0k
R8: library part CMP-0022446-5, "RES, 499, 1%, 0.1 W, AEC-Q200 Grade 0, 0603", Manufacturer=Vishay-Dale, Power_W=100mW, Supplier Part Number 1=541-499HCT-ND, TempCo="100 ppm/C", Tolerance_%=1%, Value2=0.1W, Value_Code=499R, ValueDisplayed=499
R11: library part CMP-0025381-3, "RES, 51.1 k, 0.5%, 0.1 W, 0603", Manufacturer="Yageo America", Power_W=100mW, TempCo="50 ppm/C", Tolerance_%=0.5%, Value2=0.1W, Value_Code=51k1, ValueDisplayed=51.1k
R24: library part CMP-0022855-4, "RES, 18.0, 1%, 0.1 W, 0603", Manufacturer=Yageo, Power_W=100mW, Supplier Part Number 1=311-18.0HRCT-ND, TempCo="100 ppm/C", Tolerance_%=1%, Value2=0.1W, Value_Code=18R0, ValueDisplayed=18.0
R25 R26: library part CMP-0023153-5, "RES, 4.70 k, 1%, 0.1 W, 0603", Manufacturer=Yageo, Power_W=100mW, Supplier Part Number 1=311-4.70KHRCT-ND, TempCo="100 ppm/C", Tolerance_%=1%, Value2=0.1W, Value_Code=4k70, ValueDisplayed=4.70k
R27 R28: library part CMP-0086260-1, "RES, 0, 3 W, 2512", Manufacturer="TE Connectivity", Power_W=3W, Tolerance_%=0%, Value_Code=0000, ValueDisplayed=0
TP1 TP2 TP3 TP4 TP7 TP8 TP9 TP10: library part CMP-0003907-1, "PIGTAIL", Manufacturer="Texas Instruments"
U1 U2 U3 U4: library part CMP-0081958-3, "500 mW, High-Efficiency, Low-Emissions, 5 kVRMS Isolated DC-DC Converter, DVE0016A (SO-MOD-16)", Alternate Manufacturer="Texas Instruments", Alternate PartNumber=UCC12050DVE, Operating Temperature Range="-40 to 125 C"
U5: library part CMP-0070659-2, "Ultra Low Noise, 150mA Linear Regulator for RF/Analog Circuits Requires No Bypass Capacitor, 6-pin LLP, Pb-Free", Manufacturer="Texas Instruments", PackageTopMarking=XTT*L17, PowerWise=N
U6: library part CMP-0070655-2, "Ultra Low Noise, 150mA Linear Regulator for RF/Analog Circuits Requires No Bypass Capacitor, 6-pin LLP, Pb-Free", Manufacturer="Texas Instruments", PackageTopMarking=XTT*L16, PowerWise=N
U7: library part CMP-0065668-3, "Programmable 1-PLL VCXO Clock Synthesizer with 2.5-V or 3.3-V LVCMOS Outputs, PW0014A (TSSOP-14)", Alternate Manufacturer="Texas Instruments", Alternate PartNumber=CDCE913PW, Operating Temperature Range="-40 to 85 C", Rating=Catalog
Y1: library part CMP-0078214-2, "Crystal, 16 MHz, 15 ppm, 8 pF, AEC-Q200 Grade 1, SMD", Frequency_Fixed=16MHz, Frequency Stability="150 ppm", Frequency Tolerance="10 ppm", Load Capacitance="7.36 pF", Manufacturer=NDK, Supplier Part Number 1=644-1129-1-ND

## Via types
v1: diameter 0.864, hole 0.406, Top Layer to Bottom Layer, tented both sides, 55 vias
v2: diameter 0.762, hole 0.305, Top Layer to Bottom Layer, tented both sides, 32 vias
v3: diameter 0.762, hole 0.305, Top Layer to Bottom Layer, 16 vias

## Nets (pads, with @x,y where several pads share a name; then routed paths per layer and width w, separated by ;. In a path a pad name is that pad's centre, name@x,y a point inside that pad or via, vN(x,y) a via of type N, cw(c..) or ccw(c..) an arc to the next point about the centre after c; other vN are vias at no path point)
GND: C3.2 L2.1 L4.1 L6.1 L8.1 L10.2 R28.2 | length 23.2
  Top Layer w1.2: v2(48.5,17.104) L8.1@52.487,17.104 ; v2(48.5,69.679) L4.1 ; v2(48.5,95.784) L2.1@52.287,95.784 ; v2(48.75,43.634) L6.1@52.117,43.634
  Bottom Layer w1.2: 46.22,17.104 v2(48.5,17.104) ; 46.5,43.634 v2(48.75,43.634) ; 46.5,69.679 v2(48.5,69.679) ; 46.75,95.784 v2(48.5,95.784)
  other v1: 19,76.25 22,76.25 25,76.25 28,76.25 31,76.25 34,76.25 37,76.25 20.5,79.25 23.5,79.25 29.5,79.25 32.5,79.25 35.5,79.25 41.5,79.25
LED: Q1.1 R5.2 R11.2 U1.5 U2.5 U3.5 U4.5 | length 119.9
  Top Layer w0.4: v2(60.25,13.208) U4.5 ; v2(60.25,39.698) U3.5 ; v2@60.25,65.694 U2.5 ; v2@60.25,91.749 U1.5
  Top Layer w0.6: R5.2 26.57,61.556 Q1.1 27.807,61.667 R11.2 v2(29.382,61.917)
  Signal Layer 1 w0.6: v2@29.432,61.867 v2(29.382,61.917) v2(59.5,61.917)
  Signal Layer 3 w0.4: v2(59.5,61.917) 60.25,61.917 ; v2(60.25,13.208) 60.25,29.448 v2(60.25,55.134) v2(60.25,65.633) v2(60.25,91.633)
  Bottom Layer w0.6: v2(29.382,61.917) v2@29.432,61.867
NetC1_1: C1.1 C2.1 J2.2 L3.2 TP3.1 U2.3 | length 18.8
  Top Layer w1: L3.2@53.739,68.234 U2.3 U2.3@62,68.234 ; TP3.1 55.775,67.959
  Signal Layer 3 w0.4: TP3.1 55.75,69.154 59,74.609 J2.2
NetC4_1: C4.1 C5.1 J1.2 L1.2 TP1.1 U1.3 | length 18.8
  Top Layer w1: L1.2@53.75,94.234 55.749,94.248 58.329,94.266 59.999,94.277 U1.3 ; TP1.1 55.75,94.247
  Signal Layer 3 w0.4: TP1.1@55.75,92.887 55.75,95.048 58.655,99.715 J1.2
NetC10_1: C10.1 C11.1 J7.2 L5.2 TP7.1 U3.3 | length 20.3
  Top Layer w1: L5.2@53.479,41.988 55.75,41.988 ; TP7.1 55.75,41.988 ; U3.3 61.375,41.988 55.75,41.988
  Signal Layer 3 w0.4: TP7.1 55.75,43.279 59,47.279 J7.2
NetC12_1: C12.1 C13.1 J8.2 L7.2 TP9.1 U4.3 | length 19.1
  Top Layer w1: L7.2@53.887,15.499 55.834,15.499 ; TP9.1 55.834,15.499 ; U4.3 61.376,15.499 55.834,15.499
  Signal Layer 3 w0.4: TP9.1 55.836,17.134 59,21.134 J8.2
NetC23_1: C23.1 C24.1 C25.1 C26.1 U6.1 U7.6 U7.7 | length 14.4
  Bottom Layer w0.4: U6.1 26.5,55.558 C25.1 C24.1 ; C23.1 26.5,55.208 U7.7 U7.6
NetC28_1: C28.1 U7.1 Y1.1 | length 5.3
  Bottom Layer w0.6: U7.1@27.9,51.258 C28.1 29.432,47.867 Y1.1
NetC29_1: C29.1 U7.14 Y1.3 | length 7.5
  Bottom Layer w0.5: C29.1 34.582,46.867 34.582,49.66 33.739,50.503 U7.14@33.739,51.232
  Bottom Layer w0.6: Y1.3 32.232,46.867 C29.1
NetD1_1: D1.1 R8.2 | length 1.8
  Top Layer w0.6: R8.2 D1.1
NetD1_2: D1.2 Q1.3 | length 1.8
  Top Layer w0.6: D1.2 Q1.3
NetJ1_3: J1.3 U1.1 | length 5.1
  Top Layer w0.6: U1.1@61.2,96.829 J1.3 J1.3@61.54,101.634
NetJ2_3: J2.3 U2.1 | length 4.9
  Top Layer w0.6: J2.3 61.561,75.612 U2.1
NetJ3_1: J3.1 J4.1 L9.1 R27.1
NetJ3_2: J3.2 J3.3 J3.4 J3.5 J4.2 L10.1 R28.1
NetJ7_3: J7.3 U3.1 | length 4.9
  Top Layer w0.6: J7.3 61.561,49.571 U3.1
NetJ8_3: J8.3 U4.1 | length 5.1
  Top Layer w0.6: J8.3 61.625,23.299 U4.1
NetJ11_1: J11.1 J12.1 J13.1 R25.2 | length 12.7
  Bottom Layer w0.6: J11.1 R25.2@26.61,43.905
NetJ11_2: J11.2 U7.2 | length 24.1
  Signal Layer 3 w0.5: J11.2 15.63,41.365 16.582,42.316 16.582,45.667 20.782,49.867 v2(29.182,49.867)
  Bottom Layer w0.4: U7.2 29.182,51.958 v2(29.182,49.867)
NetJ11_3: J11.3 J12.3 J13.3 R26.1 | length 12.8
  Bottom Layer w0.6: R26.1@11.092,38.825 J13.3
NetJ12_2: J12.2 U7.13 | length 21.4
  Signal Layer 3 w0.5: J12.2 21.332,43.787 21.332,45.867 23.332,47.867 30.082,47.867 v2(32.082,49.867)
  Bottom Layer w0.5: v2(32.082,49.867) 32.082,51.708 32.332,51.958 U7.13
NetJ13_2: J13.2 U7.12 | length 20.6
  Signal Layer 3 w0.5: J13.2 23.912,41.367 25.832,41.367 26.332,41.867 26.332,43.117 27.832,44.617 31.582,44.617 35.3,48.336 v2(35.3,51.267)
  Bottom Layer w0.4: U7.12 34.582,52.608 35.3,51.889 v2(35.3,51.267)
NetR4_1: R4.1 R9.2 U2.13 | length 6.9
  Top Layer w0.6: U2.13 76.849,66.964 R4.1 R9.2@77,65.624
NetR7_1: R7.1 R10.2 U1.13 | length 7.1
  Top Layer w0.6: U1.13 77.064,93.019 R7.1 R10.2
NetR15_1: R15.1 R18.2 U3.13 | length 7
  Top Layer w0.6: U3.13 76.966,40.968 R15.1 R18.2
NetR17_1: R17.1 R19.2 U4.13 | length 7.1
  Top Layer w0.6: U4.13 77.031,14.478 R17.1 R19.2
NetR20_1: R20.1 R22.2 U5.4 | length 8
  Bottom Layer w0.3: R20.1 R22.2 11.882,50.694 12.689,49.886 15.623,49.886 16.2,50.464 U5.4
NetR21_2: R21.2 R23.1 U6.4 | length 5.4
  Bottom Layer w0.4: R21.2 R23.1 14.132,54.783 14.657,54.258 U6.4
NetR24_1: R24.1 U7.9 | length 2.1
  Bottom Layer w0.4: U7.9 R24.1
PGND: C1.2 C2.2 C4.2 C5.2 C10.2 C11.2 C12.2 C13.2 C18.2 C19.2 C20.2 C21.2 C22.2 C23.2 C24.2 C25.2 C26.2 C27.2 C28.2 C29.2 L2.2 L4.2 L6.2 L8.2 Q1.2 R11.1 R22.1 R23.2 R26.2 TP1.2 TP3.2 TP7.2 TP9.2 U1.2 U1.6 U1.7 U1.8 U2.2 U2.6 U2.7 U2.8 U3.2 U3.6 U3.7 U3.8 U4.2 U4.6 U4.7 U4.8 U5.2 U5.3 U5.5 U5.7 U6.2 U6.3 U6.5 U6.7 U7.5 U7.10 Y1.2 Y1.4 | length 73.7
  Top Layer w0.6: Q1.2 27.807,63.567 R11.1
  Top Layer w1: L6.2@53.542,43.634 61.499,43.634 U3.2 ; L2.2 61.4,95.784 U1.2 ; L4.2@53.701,69.679 U2.2@62,69.634 ; L8.2 61.539,17.104 U4.2
  Bottom Layer w0.3: Y1.4 Y1.2
  Bottom Layer w0.4: v2(13.282,50.667) R22.1@13.282,51.617 ; R22.1 R22.1@13.282,51.617 ; R23.2 16.282,54.858 18.05,54.858 U6.7 ; U5.7@17.332,51.617 R22.1@13.282,51.617 ; U5.7 U5.2 U5.3 C19.2 C22.2 C21.2 C20.2 ; C27.2 18.1,56.936 U6.7 ; U7.5 21.4,53.908 C26.2 21.05,54.258 U6.3 U6.2 U6.7 ; U7.10 34.895,53.908 36.186,52.617 v2(37.082,52.617)
  Bottom Layer w0.6: C28.2 29.432,46.867 Y1.4 ; Y1.2 32.232,47.867 C29.2
  other v1: 6.423,9.036 14.423,9.036 22.423,9.036 30.423,9.036 38.423,9.036 46.423,9.036 54.423,9.036 6.423,17.036 14.423,17.036 22.423,17.036 30.423,17.036 38.423,17.036 6.423,25.036 14.423,25.036 22.423,25.036 30.423,25.036 38.423,25.036 54.423,25.036 6.423,33.036 14.423,33.036 22.423,33.036 30.423,33.036 6.423,41.036 22.423,41.036 30.423,41.036 6.423,49.036 14.423,49.036 54.423,49.036 6.423,57.036 22.423,57.036 30.423,57.036 6.423,65.036 14.423,65.036 22.423,65.036 30.423,65.036 22.423,73.036 30.423,73.036 54.423,81.036 54.423,89.036 22.423,97.036 30.423,97.036 38.423,97.036
  other v2: 61.75,7.384 61.655,34.384 21.038,51.058 20.082,54.258 61.654,60.634 61.625,86.384
SGND: C6.2 C7.2 C8.2 C9.2 C14.2 C15.2 C16.2 C17.2 J5.2 J6.2 J9.2 J10.2 R1.1 R2.1 R9.1 R10.1 R12.1 R13.1 R18.1 R19.1 TP2.2 TP4.2 TP8.2 TP10.2 U1.9 U1.10 U1.11 U1.12 U1.15 U1.16 U2.9 U2.10 U2.11 U2.12 U2.15 U2.16 U3.9 U3.10 U3.11 U3.12 U3.15 U3.16 U4.9 U4.10 U4.11 U4.12 U4.15 U4.16
  other v2: 71.6,7.384 71.25,34.384 71.375,60.454 71.5,86.384
  other v3: 77.752,4.75 90,4.75 77.752,24.107 90,24.107 77.752,31.5 90,31.5 77.703,50.671 90,50.671 90,57.5 77.752,58 77.703,77 90,77 77.703,83.5 90,83.5 77.703,102.671 90,102.671
SYNC: R24.2 U1.4 U2.4 U3.4 U4.4 | length 201
  Top Layer w0.4: v2(58,14.161) 59.481,14.161 59.797,14.478 U4.4 ; v2(58,40.453) 59.277,40.453 59.792,40.968 U3.4 ; v2(58.29,66.634) 59.5,66.634 59.83,66.964 U2.4 ; v2(58.29,92.634) 59.81,92.634 60.31,93.019 U1.4
  Signal Layer 3 w0.4: 43.75,59.884 40.75,59.884 39.986,59.384 39.986,55.634 v2(38.236,54.558) ; v2(58,14.161) 56.789,12.767 44.5,12.767 38.249,32.634 v2(38.236,54.558) ; v2(58,40.453) 57,39.384 57,35.134 55.5,33.634 50.65,33.634 48.85,33.634 48.25,33.034 48.25,30.434 47.65,29.834 46.45,29.834 45.85,30.434 45.85,33.634 45.85,36.584 45.25,37.184 44.05,37.184 43.45,36.584 43.45,34.234 42.85,33.634 42.25,33.634 41.5,33.634 40,34.884 40,52.384 v2(38.236,54.558) ; v2(58.29,66.634) 58.33,61.724 ; v2(58.29,92.634) 57,91.134 50.5,91.134 49,88.884 46.5,88.884 45,91.134 42,91.134 39.25,87.134 39.25,63.634 38.25,61.66 v2(38.236,54.558)
  Bottom Layer w0.6: R24.2 v2(38.236,54.558)
VDD: C19.1 C20.1 C21.1 C22.1 R25.1 U5.1 U7.3 | length 16.8
  Bottom Layer w0.4: U5.1 18.75,52.608 26.61,52.608 ; R25.1 26.66,52.558 26.61,52.608 ; U7.3 26.61,52.608
VIN: C3.1 C18.1 C27.1 L1.1 L3.1 L5.1 L7.1 L9.2 R5.1 R8.1 R20.2 R21.1 R27.2 U5.6 U6.6 | length 70.1
  Top Layer w0.6: v2(16.9,59.517) 20.66,59.517 R5.1 25.17,58.529 25.332,58.367 44.832,58.367
  Top Layer w1.2: 46,94.289 L1.1@52.304,94.234 ; 46.75,68.234 L3.1
  Top Layer w1.25: 45.75,15.499 L7.1@52.462,15.499 ; 46.75,41.988 L5.1@52.054,41.988
  Bottom Layer w0.5: U5.6 15.365,53.192 C18.1 R20.2 13.282,54.808 13.057,55.033 13.057,57.792 13.382,58.117 16.889,58.117
  Bottom Layer w0.6: R21.1 C27.1 ; v2(16.9,59.517) 16.889,58.117 C27.1 ; U6.6 16.95,57.049 C27.1
VISO1: C8.1 C9.1 J6.1 R2.2 R7.2 TP2.1 U1.14 | length 19.9
  Top Layer w1.2: U1.14 J6.1
VISO2: C6.1 C7.1 J5.1 R1.2 R4.2 TP4.1 U2.14 | length 20.1
  Top Layer w1.2: U2.14 J5.1
VISO3: C14.1 C15.1 J9.1 R12.2 R15.2 TP8.1 U3.14 | length 19.8
  Top Layer w1.2: U3.14@71.674,42.238 J9.1
VISO4: C16.1 C17.1 J10.1 R13.2 R17.2 TP10.1 U4.14 | length 20.1
  Top Layer w1.2: U4.14 J10.1
pads on no net: J1.1 J2.1 J7.1 J8.1 U7.4 U7.8 U7.11
copper on no net: | length 42.4
  Signal Layer 3 w0.4: 43.75,59.884 44.25,59.884 44.5,59.884 44.75,59.884 45.3,59.884 45.75,59.884 46,59.884 46.25,59.884 46.5,59.884 46.75,59.884 46.9,59.884 47,59.884 47.25,59.884 47.5,59.884 47.75,59.884 47.9,59.884 48,59.884 48.25,59.884 48.4,59.884 48.5,59.884 48.75,59.884 48.9,59.884 49,59.884 49.25,59.884 49.4,59.884 49.825,59.884 50.25,60.309 50.25,65.009 50.675,65.434 51.525,65.434 51.95,65.009 51.95,59.884 51.95,56.959 52.375,56.534 53.225,56.534 53.65,56.959 53.65,59.884 53.65,65.009 54.075,65.434 54.925,65.434 55.35,65.009 55.35,60.309 55.775,59.884 57,59.884 58.33,61.724

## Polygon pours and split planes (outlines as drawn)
SGND on Top Layer "Top Layer-SGND" (solid, remove dead copper, pour order 36): 97.574,0 70.5,0 70.5,106 97.574,106
PGND on Top Layer "Top Layer-PGND" (solid, remove dead copper, pour order 34): 0.044,106 62.441,106 62.441,-0.083 0.044,-0.083
VIN on Top Layer "Top Layer-VIN" (solid, remove dead copper, pour order 8): 15.25,90.384 47.5,90.384 47.5,82.884 15.25,82.884
NetJ3_2 on Top Layer "Top Layer-NetJ3_2" (solid, remove dead copper, pour order 4): 0.192,81.884 14.987,81.884 14.987,70.384 0.192,70.384
NetJ3_1 on Top Layer "Top Layer-NetJ3_1" (solid, remove dead copper, pour order 2): 0.25,100.384 0.25,82.384 14.987,82.384 14.987,100.384
SGND on Signal Layer 1 "Signal Layer 1-SGND" (solid, remove dead copper, pour order 16): 97.5,0 70.5,0 70.5,106 97.5,106
PGND on Signal Layer 1 "Signal Layer 1-PGND" (solid, remove dead copper, pour order 14): 0.047,105.917 62.478,105.917 62.478,-0.084 0.047,-0.084
no net on Signal Layer 1 "Signal Layer 1-No Net" (solid, remove dead copper, pour order 12): 44,130.25
PGND on Signal Layer 2 "Signal Layer 2-PGND" (solid, remove dead copper, pour order 20): 62.5,-0.1 0.046,-0.1 0.046,130.797 62.5,130.797
SGND on Signal Layer 2 "Signal Layer 2-SGND" (solid, remove dead copper, pour order 18): 70.5,106 97.423,106 97.423,0.019 70.5,0.019
SGND on Signal Layer 3 "Signal Layer 3-SGND" (solid, remove dead copper, pour order 24): 97.701,0.011 70.502,0.011 70.502,106 97.701,106
PGND on Signal Layer 3 "Signal Layer 3-PGND" (solid, remove dead copper, pour order 22): -0.08,105.923 62.518,105.923 62.518,-0.083 -0.08,-0.083
SGND on Signal Layer 4 "Signal Layer 4-SGND" (solid, remove dead copper, pour order 28): 97.522,0.009 70.5,0.009 70.5,106 97.522,106
PGND on Signal Layer 4 "Signal Layer 4-PGND" (solid, remove dead copper, pour order 26): 0.068,105.896 62.522,105.896 62.522,-0.093 0.068,-0.093
NetJ3_2 on Bottom Layer "Bottom Layer-NetJ3_2" (solid, remove dead copper, pour order 30): 0.25,100.384 15,100.384 15,70.134 14.75,70.384 0.25,70.384
PGND on Bottom Layer "Bottom Layer-PGND" (solid, remove dead copper, pour order 38): 0.25,-0.001 62.422,-0.001 62.422,106 0.25,106
SGND on Bottom Layer "Bottom Layer-SGND" (solid, remove dead copper, pour order 32): 70.5,106 97.556,106 97.556,0.037 70.5,0.037

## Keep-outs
Keep-Out Layer:
  text ".Layer_Name" at 14.656,-21.806 h0.8

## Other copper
Top Layer:
  region net VISO4: 92.5,16.634 78.75,16.634 78.75,13.384 92.5,13.384
  region net VISO3: 92.5,43.134 78.75,43.134 78.75,39.884 92.5,39.884
  region net VISO1: 78.73,95.134 78.73,91.884 92.25,91.884 92.25,95.134
  region net VISO2: 78.75,69.134 92.5,69.134 92.5,65.884 78.75,65.884
  region net GND: 15.25,81.884 15.25,74.134 43,74.134 43,81.884
  region net VIN: 43.75,94.884 47.5,94.884 47.5,14.884 43.75,14.884
  text ".Layer_Name" at 14.656,-21.806 h0.8
Bottom Layer:
  region net GND: 47.5,96.634 40,96.634 40,82.192 15.5,82.192 15.5,73.942 40,73.942 40,16.384 47.5,16.384
  text ".Layer_Name" at 14.656,-21.806 h0.8

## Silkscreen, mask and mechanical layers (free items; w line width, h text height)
Top Overlay:
  text "OFF" at 55.339,103.5 h1.5
  text "ON" at 59.5,103.5 h1.5
  text "EN 1" at 63.25,101.126 h1.25
  text "-" at 95.5,97.036 h3.5
  text "+" at 95.25,93.285 h2.7
  text "VIN" at 4.75,88.209 h1.52
  text "ISO OUT / #1" at 86.5,86.884 h1.52
  text "+" at 1.25,83 h2.7
  text "-" at 1.5,79.159 h3.5
  text "OFF" at 55.623,77.5 h1.5
  text "ON" at 59.791,77.5 h1.5
  text "VIN" at 4.847,75.75 h1.52
  text "EN 2" at 63.5,75.126 h1.25
  text "-" at 95.5,71.154 h3.5
  text "+" at 95.25,67.509 h2.7
  text "Green = Ext SYNC" at 7.832,64.067 h1
  text "ISO OUT / #2" at 86.25,60.884 h1.52
  text "OFF" at 55.641,51.633 h1.5
  text "ON" at 59.829,51.633 h1.5
  text "EN 3" at 63.5,49.115 h1.25
  text "-" at 95.5,45.045 h3.5
  text "1" at 26.332,43.117 h2.5
  text "+" at 95.25,41.647 h2.7
  text "0" at 26.294,38.167 h2.5
  text "ISO OUT / #3" at 86.25,35.134 h1.52
  text "S0" at 12.796,34.867 h1.52
  text "S1" at 18.082,34.867 h1.52
  text "S2" at 22.832,34.867 h1.52
  text "OFF" at 55.595,25.25 h1.5
  text "ON" at 59.839,25.25 h1.5
  text "EN 4" at 63.75,22.865 h1.25
  text "-" at 95.5,18.509 h3.5
  text "+" at 95.25,15.072 h2.7
  text "ISO OUT / #4" at 85.5,8.634 h1.52
  text "'.PRJ_Number'.PCB_Rev" at 18.059,3.5 h2.75
  text ".Layer_Name" at 14.656,-21.806 h0.8
Bottom Overlay:
  text ".Layer_Name" at 14.656,-21.806 h0.8
Top Paste:
  text ".Layer_Name" at 14.656,-21.806 h0.8
Bottom Paste:
  text ".Layer_Name" at 14.656,-21.806 h0.8
Top Solder:
  text ".Layer_Name" at 14.656,-21.806 h0.8
  text ".Layer_Name" at 14.656,-21.806 h0.8
Bottom Solder:
  text ".Layer_Name" at 14.656,-21.806 h0.8
Drill Guide:
  text ".Layer_Name" at 14.656,-21.806 h0.8
M1 Board Outline:
  the board outline again, w0.254
  text ".Layer_Name" at 14.656,-21.806 h0.8
M2 Board Dimensions:
  rectangle: 0,-6.985 3.175,-3.81
  rectangle: 3.175,-10.16 12.7,-6.985
  lines w0.178: 0,-6.985 25.4,-6.985 ; 3.175,-10.16 3.175,-3.81 ; 6.35,-10.16 6.35,-3.81 ; 12.7,-10.16 12.7,-3.81 ; 19.05,-10.16 19.05,-3.81 ; 0,-10.16 25.4,-10.16 25.4,-3.81 0,-3.81 0,-10.16
  text ".Layer_Name" at 14.656,-21.806 h0.8
M3 3D STEP Top:
  text ".Layer_Name" at 14.656,-21.806 h0.8
M4 3D STEP Bottom:
  text ".Layer_Name" at 14.656,-21.806 h0.8
M5 Assembly Top:
  lines w0.254: -7.417,-23.626 160.223,-23.626 ; -7.417,-18.462 160.274,-18.462 ; -7.417,-13.297 -7.417,-28.791 94.31,-28.791 160.274,-28.791 160.274,-13.297 -7.404,-13.297 -7.404,-28.791 32.614,-28.791 ; 55.194,-28.791 55.194,-13.297 ; 87.376,-18.462 87.376,-13.297 ; 108.712,-18.462 108.712,-13.297 ; 124.511,-28.956 124.511,-23.804
  text "COMPONENTS MARKED 'DNP' SHOULD NOT BE POPULATED." at 29.299,-8.09 h0.8
  text "ASSEMBLY VARIANT:" at 29.286,-11.024 h0.8
  text ".VariantName" at 55.601,-11.024 h0.8
  text "PCB VIEWED FROM TOP SIDE" at -5.804,-16.654 h0.8
  text "BOARD #:" at 57.099,-16.654 h0.8
  text ".PRJ_Number" at 70.955,-16.654 h0.8
  text "REV:" at 92.405,-16.654 h0.8
  text ".PCB_Rev" at 99.809,-16.654 h0.8
  text "SVN REV:" at 113.69,-16.654 h0.8
  text ".VersionControl_RevNumber" at 126.543,-16.654 h0.8
  text "TID #:" at 57.099,-21.819 h0.8
  text ".TID" at 70.955,-21.819 h0.8
  text "PLOT NAME =" at -5.804,-27.034 h0.8
  text ".plot_File_Name" at 14.656,-27.034 h0.8
  text "GENERATED    :" at 57.15,-27.034 h0.8
  text ".Print_Date" at 79.235,-27.034 h0.8
  text ".Print_Time" at 97.752,-27.034 h0.8
  text "TEXAS INSTRUMENTS" at 129.87,-27.034 h0.8
M6 Assembly Bottom:
  lines w0.254: -7.429,-18.474 160.261,-18.474 ; -7.379,-23.639 160.261,-23.639 ; 28.334,-28.969 28.334,-23.817 ; 44.133,-18.474 44.133,-13.31 ; 65.468,-18.474 65.468,-13.31 ; 97.65,-28.804 97.65,-13.31 ; 120.231,-28.804 160.249,-28.804 160.249,-13.31 -7.429,-13.31 -7.429,-28.804 58.534,-28.804 160.261,-28.804 160.261,-13.31
  text "COMPONENTS MARKED 'DNP' SHOULD NOT BE POPULATED." at 154.991,-8.077 h0.8
  text ".VariantName" at 128.473,-11.024 h0.8
  text "ASSEMBLY VARIANT:" at 154.864,-11.024 h0.8
  text ".VersionControl_RevNumber" at 26.302,-16.667 h0.8
  text "SVN REV:" at 39.154,-16.667 h0.8
  text ".PCB_Rev" at 53.035,-16.667 h0.8
  text "REV:" at 60.439,-16.667 h0.8
  text ".PRJ_Number" at 81.89,-16.667 h0.8
  text "BOARD #:" at 95.745,-16.667 h0.8
  text "PCB VIEWED FROM BOTTOM SIDE" at 158.648,-16.667 h0.8
  text ".TID" at 81.89,-21.831 h0.8
  text "TID #:" at 95.745,-21.831 h0.8
  text "TEXAS INSTRUMENTS" at 22.974,-27.047 h0.8
  text ".Print_Time" at 55.093,-27.047 h0.8
  text ".Print_Date" at 73.609,-27.047 h0.8
  text "GENERATED    :" at 95.694,-27.047 h0.8
  text ".plot_File_Name" at 138.189,-27.047 h0.8
  text "PLOT NAME =" at 158.648,-27.047 h0.8
M9 Title Sheet:
  drawing of 57 lines, arcs and shapes, not listed
  text "1" at 18.792,204.127 h1.78
  text "2" at 82.182,204.127 h1.78
  text "3" at 145.411,204.127 h1.78
  text "4" at 209.08,204.127 h1.78
  text "5" at 272.555,204.127 h1.78
  text "6" at 336.182,204.127 h1.78
  text "A" at -10.579,175.095 h1.78
  text "A" at 365.341,175.095 h1.78
  text "B" at -10.579,114.643 h1.78
  text "B" at 365.341,114.643 h1.78
  text "C" at -10.579,54.318 h1.78
  text "C" at 365.341,54.318 h1.78
  text "PROJECT TITLE:" at 288.125,7.048 h1.14
  text ".PRJ_Title" at 289.395,3.662 h1.78
  text "DESIGNED FOR:" at 288.125,-0.597 h1.14
  text ".PRJ_Customer" at 289.395,-4.153 h1.78
  text "D" at -10.579,-5.88 h1.78
  text "D" at 365.341,-5.88 h1.78
  text "FILE NAME:" at 288.125,-8.217 h1.14
  text ".PCB_File_Name_No_Path" at 289.395,-11.265 h1.78
  text "Texas Instruments (TI) and/or its licensors do not warrant the accuracy or completeness of this specification" at 161.9,-15.376 h1.14
  text "ENGINEER:" at 288.125,-15.583 h1.14
  text "LAYOUT BY:" at 326.352,-15.583 h1.14
  text "or any information contained therein. TI and/or its licensors do not warrant that this design will meet" at 160.757,-18.237 h1.14
  text ".PRJ_Engineer" at 289.395,-19.52 h1.78
  text ".PCB_Layout" at 327.635,-19.52 h1.78
  text "the specifications, will be suitable for your application or fit for any particular purpose, or will operate in" at 160.757,-21.099 h1.14
  text ".Layer_Name" at 14.656,-21.806 h0.8
  text "ALTIUM DESIGNER VERSION:" at 326.352,-23.457 h1.14
  text "an implementation. TI and/or its licensors do not warrant that the design is production worthy. You should" at 160.757,-23.961 h1.14
  text "completely validate and test your design implementation to confirm the system functionality for your application." at 161.9,-26.822 h1.14
  text ".print_Scale" at 289.395,-26.843 h1.78
  text ".Application_BuildNumber" at 327.635,-26.843 h1.78
  text "1" at 18.792,-32.093 h1.78
  text "2" at 82.182,-32.093 h1.78
  text "3" at 145.411,-32.093 h1.78
  text "4" at 209.08,-32.093 h1.78
  text "5" at 272.555,-32.093 h1.78
  text "6" at 336.182,-32.093 h1.78
M10 Fab Notes:
  lines w0.508: 287.122,22.123 363.093,22.123
  text ".Layer_Name" at 14.656,-21.806 h0.8
M11 Gerber Information:
  lines w0.254: -7.417,-23.626 160.223,-23.626 ; -7.417,-18.462 160.274,-18.462 ; -7.417,-13.297 -7.417,-28.791 94.31,-28.791 160.274,-28.791 160.274,-13.297 -7.404,-13.297 -7.404,-28.791 32.614,-28.791 ; 55.194,-28.791 55.194,-13.297 ; 87.376,-18.462 87.376,-13.297 ; 108.712,-18.462 108.712,-13.297 ; 124.511,-28.956 124.511,-23.804
  text "ALL ARTWORK VIEWED FROM TOP SIDE" at -5.804,-16.654 h0.8
  text "BOARD #:" at 57.099,-16.654 h0.8
  text ".PRJ_Number" at 70.955,-16.654 h0.8
  text "REV:" at 92.405,-16.654 h0.8
  text ".PCB_Rev" at 99.809,-16.654 h0.8
  text "SVN REV:" at 113.69,-16.654 h0.8
  text ".VersionControl_RevNumber" at 126.543,-16.654 h0.8
  text "LAYER NAME =" at -5.804,-21.806 h0.8
  text "TID #:" at 57.099,-21.819 h0.8
  text ".TID" at 70.955,-21.819 h0.8
  text "PLOT NAME =" at -5.804,-27.034 h0.8
  text ".plot_File_Name" at 14.656,-27.034 h0.8
  text "GENERATED    :" at 57.15,-27.034 h0.8
  text ".Print_Date" at 79.235,-27.034 h0.8
  text ".Print_Time" at 97.752,-27.034 h0.8
  text "TEXAS INSTRUMENTS" at 129.87,-27.034 h0.8
M12 Stackup:
  text ".Layer_Name" at 14.656,-21.806 h0.8
M13 Component Bodies Top:
  text ".Layer_Name" at 14.656,-21.806 h0.8
M14 Component Bodies Bottom:
  text ".Layer_Name" at 14.656,-21.806 h0.8
M15 Courtyards Top:
  text ".Layer_Name" at 14.656,-21.806 h0.8
M16 Courtyards Bottom:
  text ".Layer_Name" at 14.656,-21.806 h0.8
Drill Drawing:
  text ".Layer_Name" at 14.656,-21.806 h0.8
M17 Embedded Cavity:
  text ".Layer_Name" at 14.656,-21.806 h0.8
M18 Embedded Assembly:
  text ".Layer_Name" at 14.656,-21.806 h0.8
M19 Embedded Keepout:
  text ".Layer_Name" at 14.656,-21.806 h0.8

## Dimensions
0,-10.16 to 25.4,-10.16 on M2 Board Dimensions
0,0 to 0.25,106 on M2 Board Dimensions
0,0 to 97.5,0 on M2 Board Dimensions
